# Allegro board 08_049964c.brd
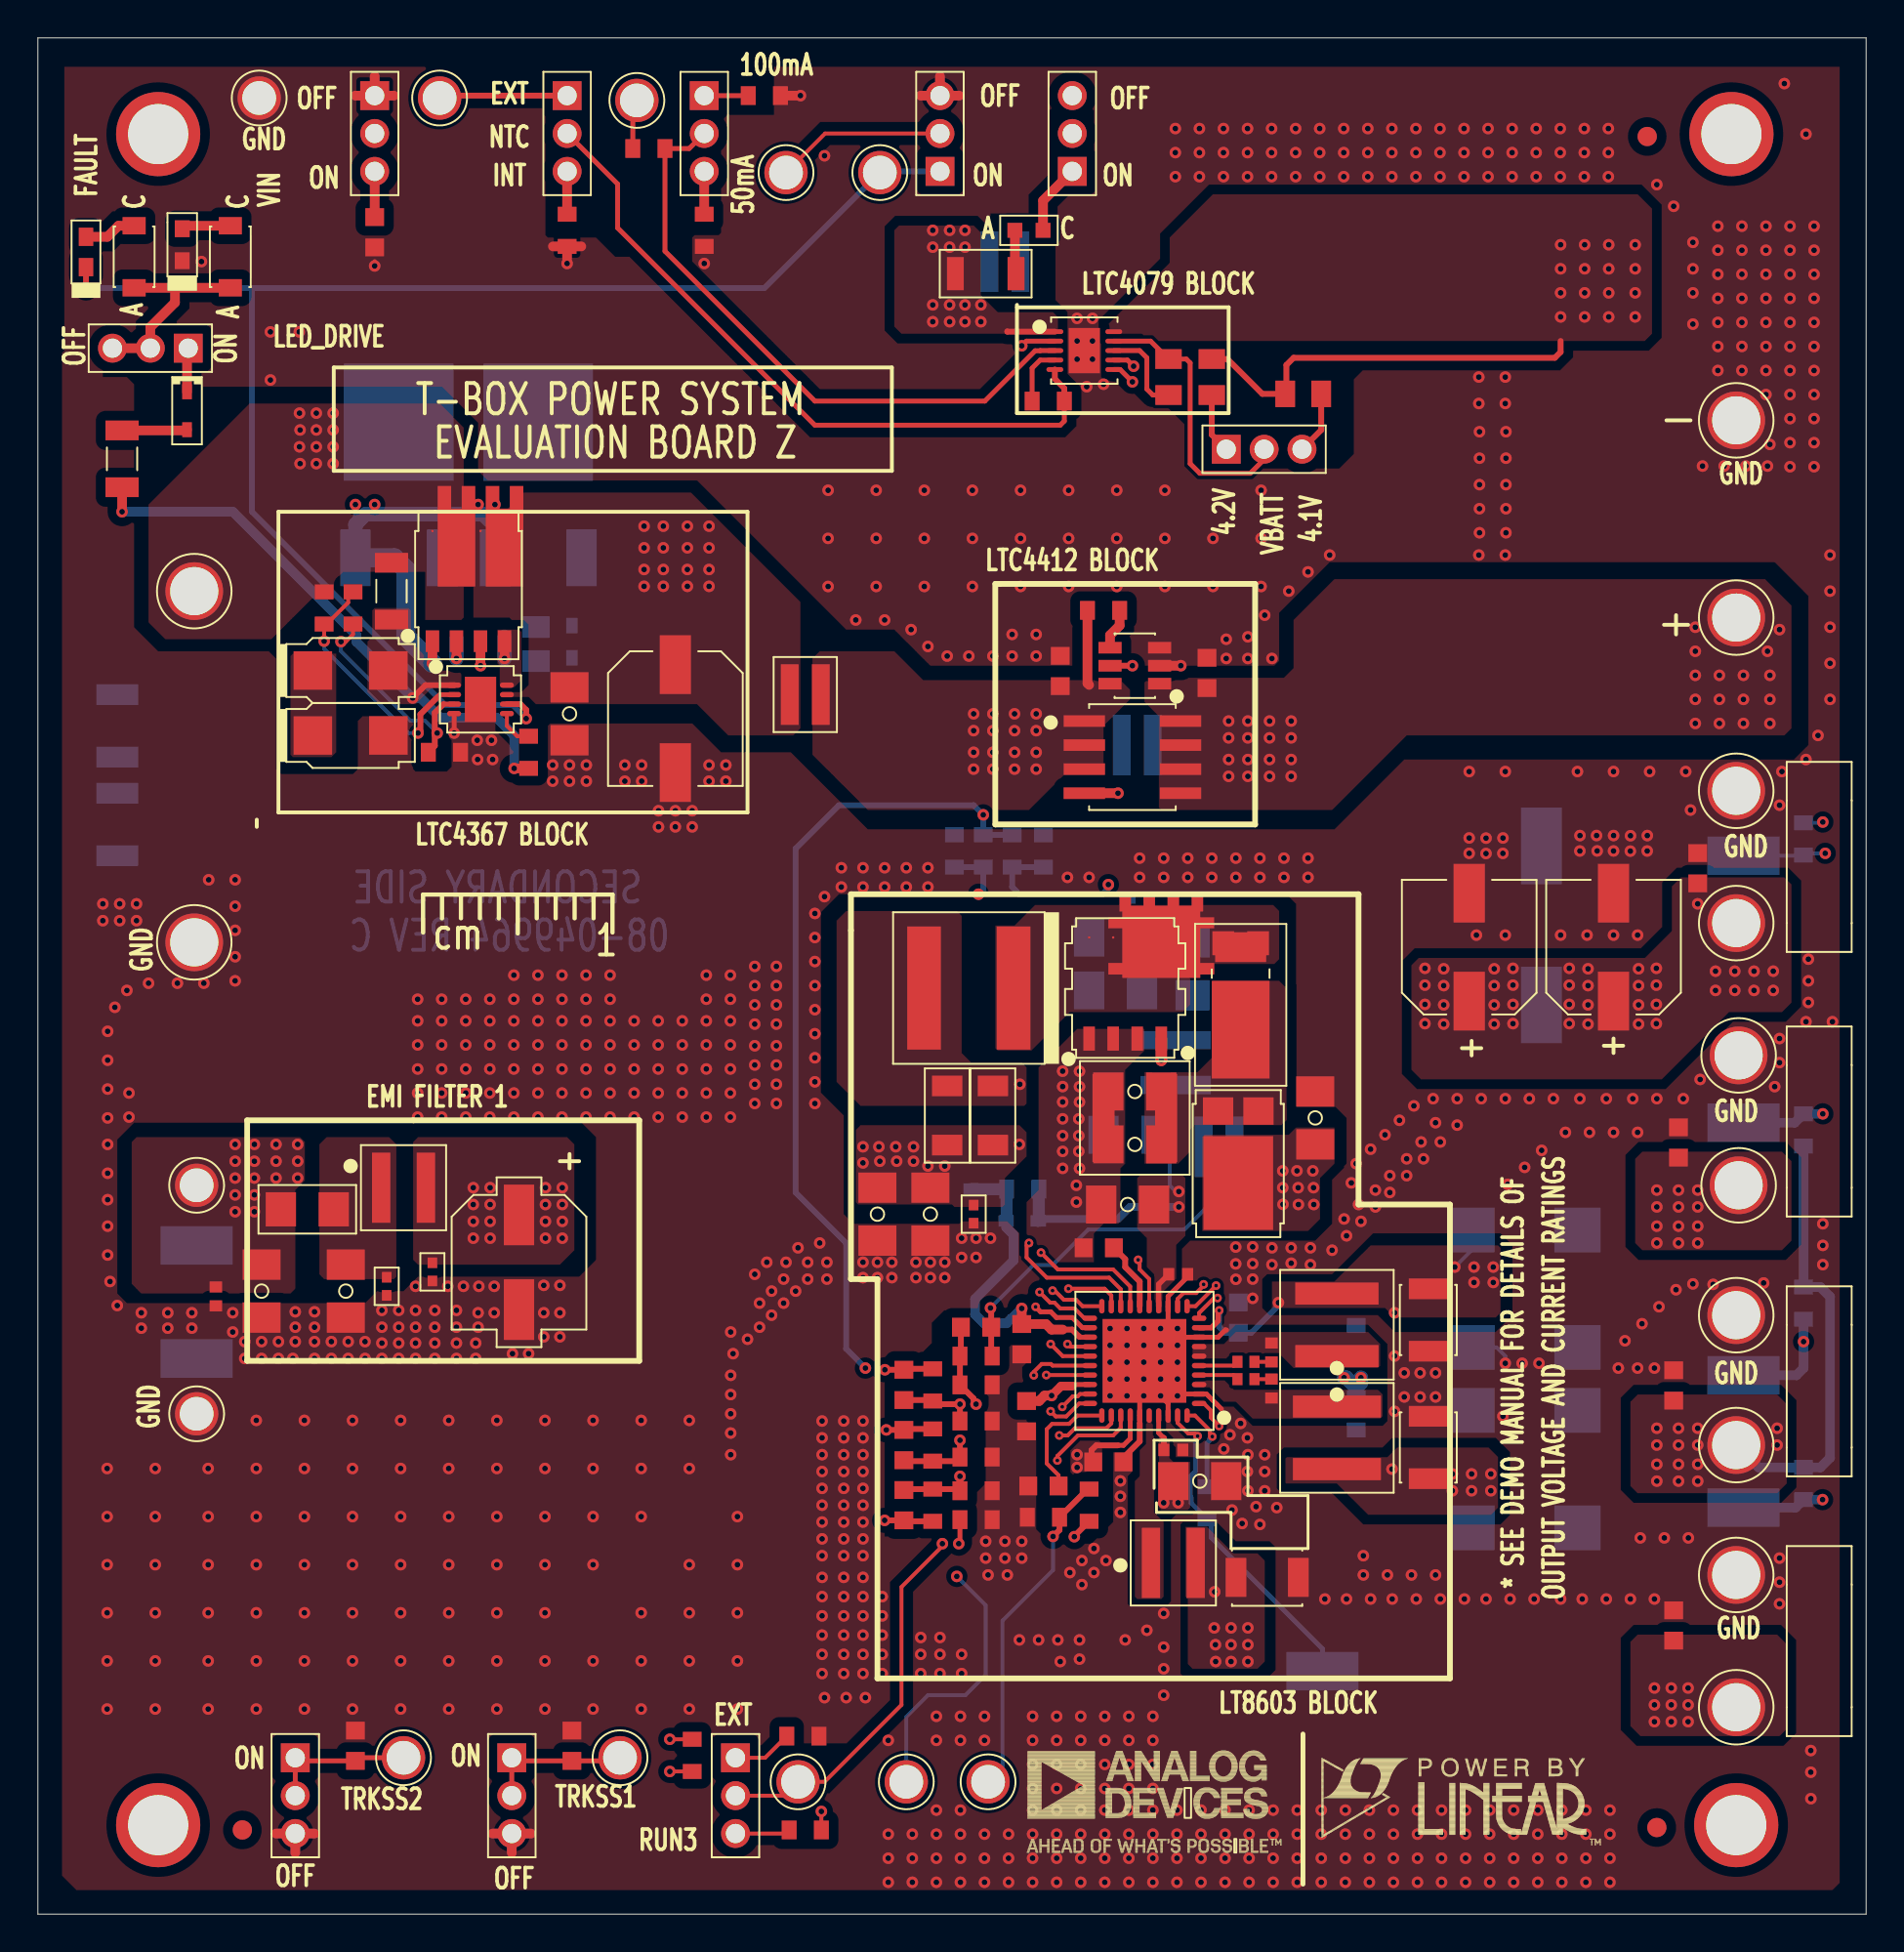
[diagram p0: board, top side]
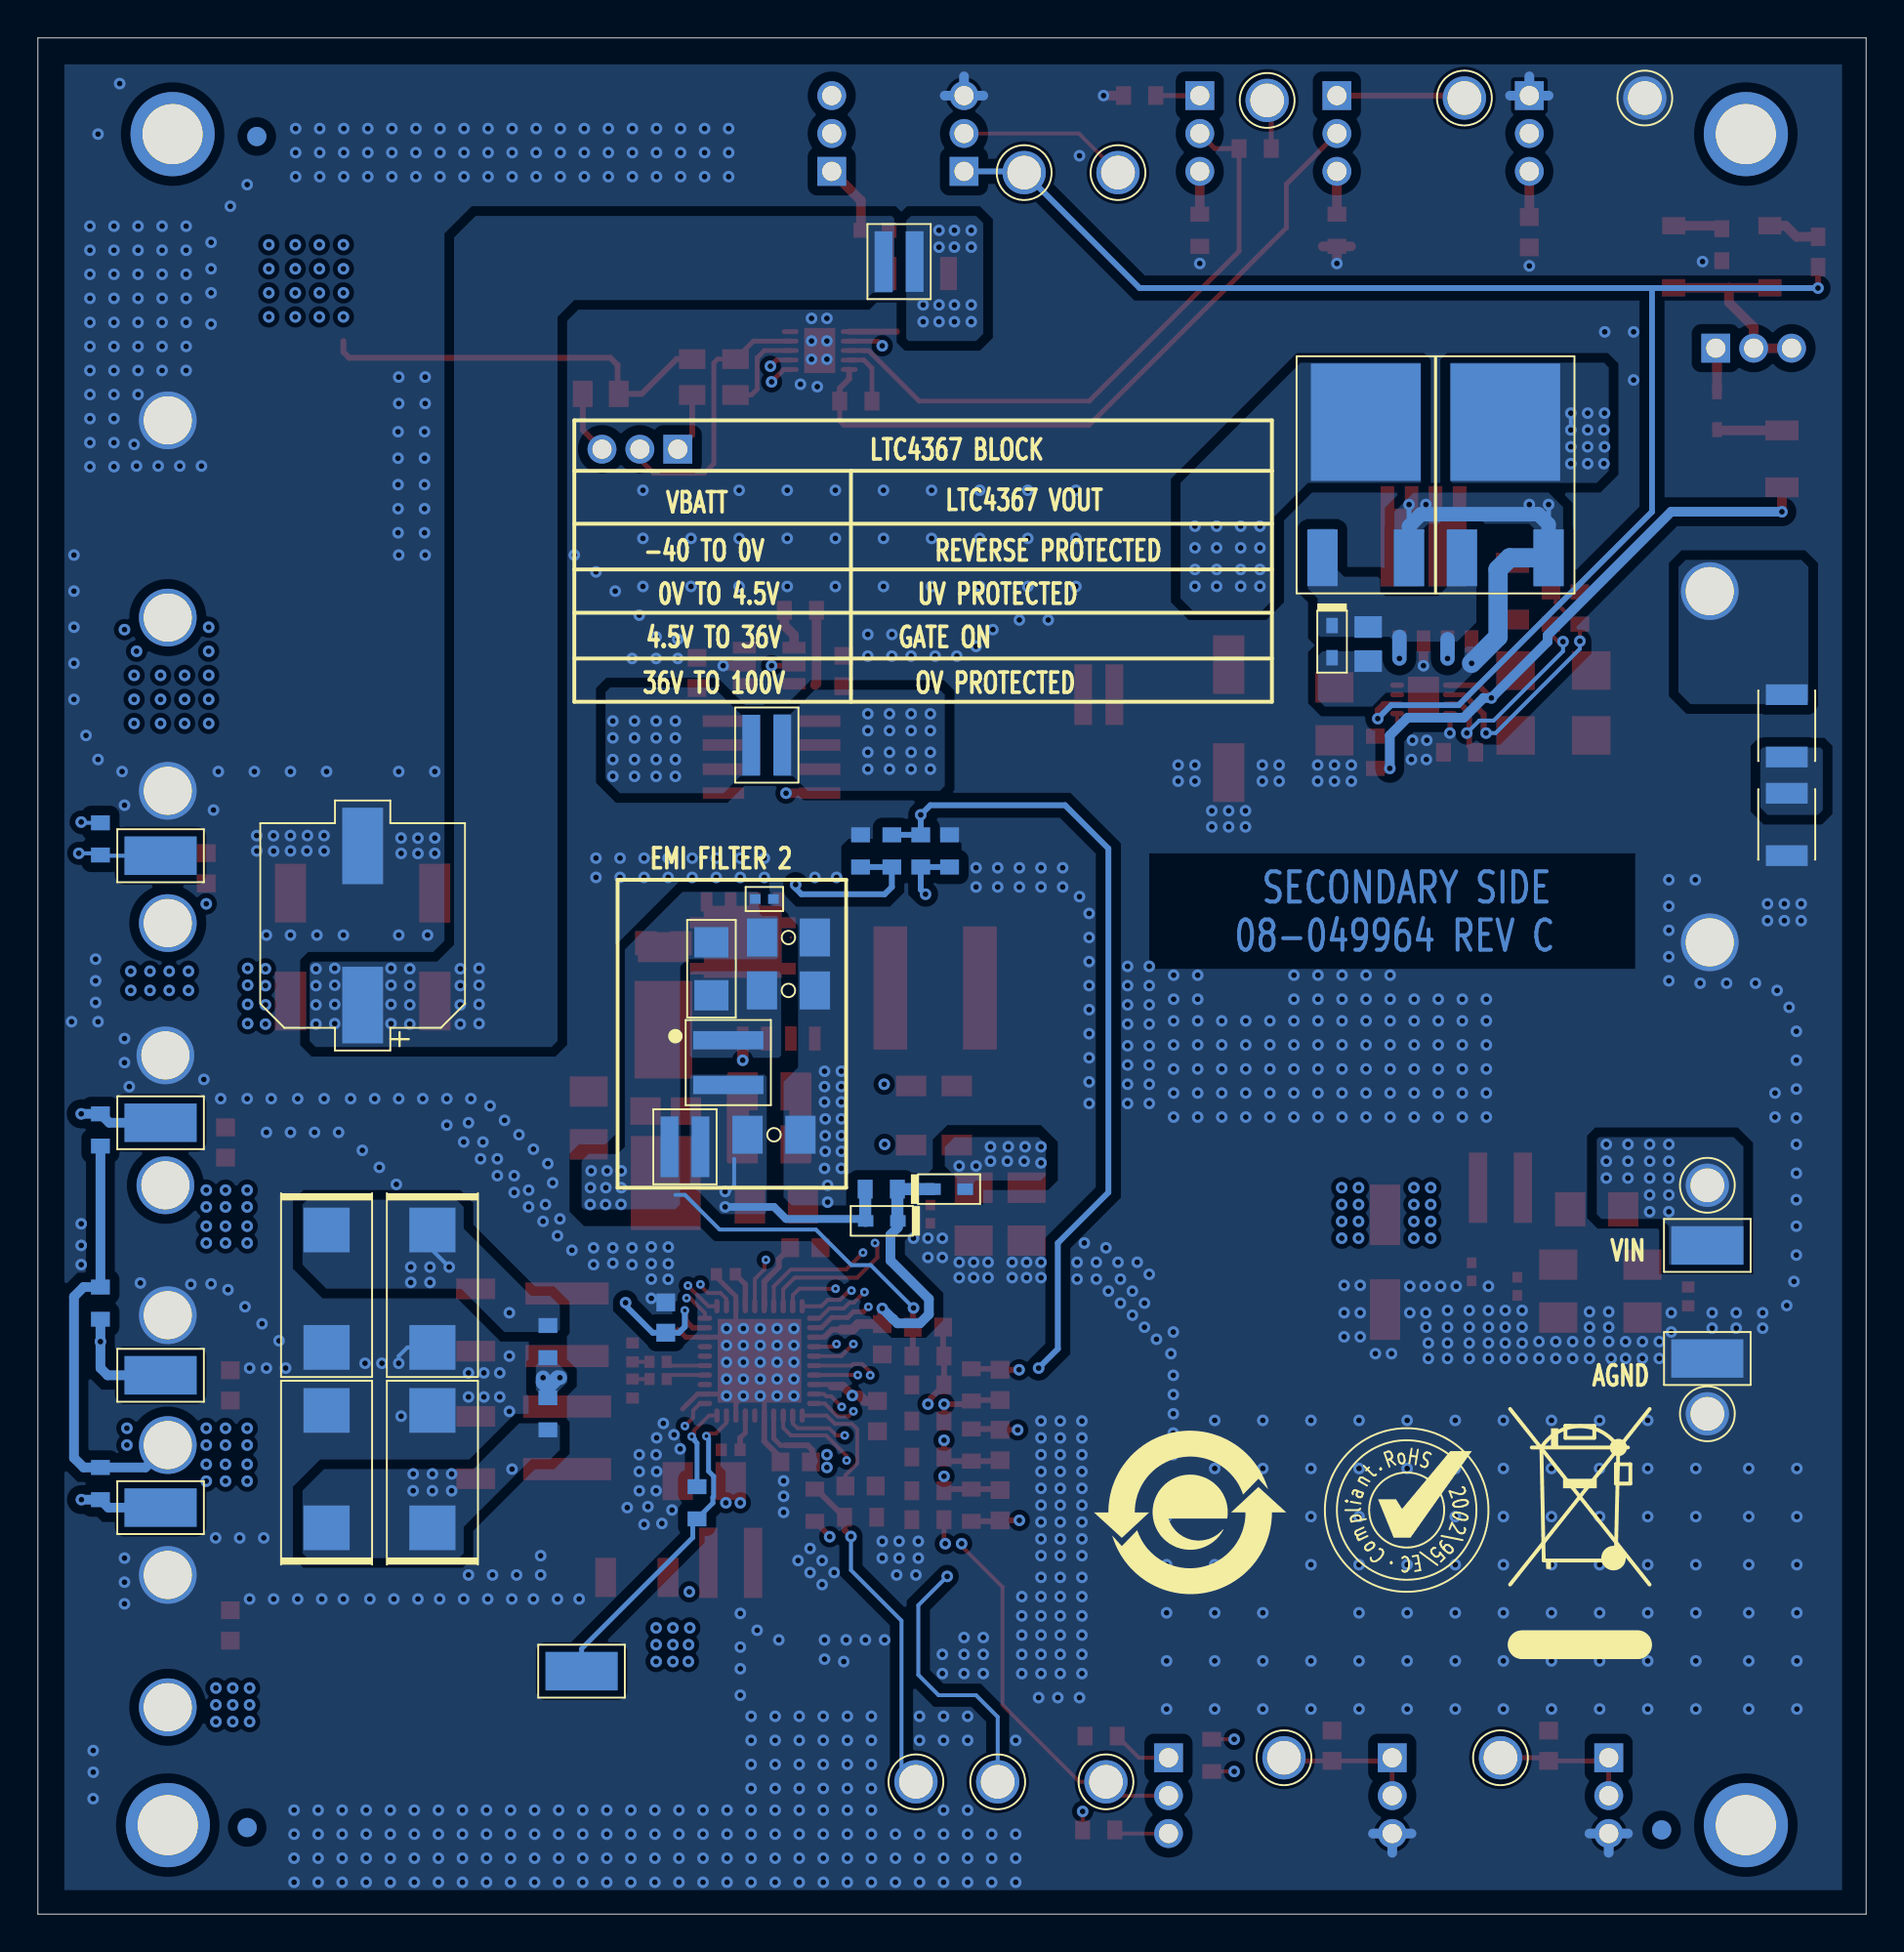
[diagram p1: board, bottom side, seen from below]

Outline 96.52 x 99.06 mm; copper layers: TOP, L2_GND, L3_PWR, BOTTOM. Coordinates in mm from the lower left corner of the outline.
Outline path: 0,99.06 0,0 96.52,0 96.52,99.06 0,99.06

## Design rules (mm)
constraint set DEFAULT: min track width 0.203

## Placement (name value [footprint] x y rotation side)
C1  10UF  [C1206H71]  44.32 36.96 90 top
C2  10UF  [C1206H71]  47.12 36.96 90 top
C4  0.047UF  [C0603]  17.78 88.8 90 top
C6  10UF  [C1206H71]  67.44 42.04 270 top
C7  0.1UF  [C0603]  61.72 65.53 270 top
C8  0.1UF  [C0603]  53.98 65.63 270 top
C9  0.1UF  [C0402]  9.4 32.61 90 top
C10  0.047UF  [C0603]  28.19 8.89 90 top
C11  0.047UF  [C0603]  16.76 8.89 90 top
C12  22UF  [CPLSMSQ260H217]  25.4 34.42 270 top
C13  10UF  [C1206H71]  11.81 32.89 90 top
C14  10UF  [C1206H71]  16.26 32.89 90 top
C15  10UF  [C1206H71]  61.34 22.86 180 top
C16  10UF  [C1206H71]  57.53 37.46 0 top
C17  1UF  [C0603]  51.94 30.35 270 top
C18  0.022uF  [C0603]  63.37 31.5 270 bottom
C19  4.7UF  [C0603]  52.2 26.29 90 top
C20  0.1UF  [C0402]  60.2 33.78 180 top
C21  4.7UF  [C0603]  56.01 35.18 0 top
C22  1500PF  [C0603]  53.09 22.61 180 top
C23  0.1UF  [C0402]  59.94 24.51 180 top
C24  0.1UF  [C0402]  65.13 27.75 270 top
C25  0.1UF  [C0402]  65.13 29.65 90 top
C26  10UF  [C0603]  56.52 23.88 180 top
C27  22PF  [C0603]  45.72 21.59 270 top
C28  4.7PF  [C0603]  45.72 27.94 90 top
C29  2.2PF  [C0603]  45.72 24.77 90 top
C30  0.022uF  [C0603]  49.53 30.99 0 top
C31  10UF  [C1206H71]  57.91 40.64 0 top
C32  100UF  [C1210H106]  64.9 17.78 180 top
C33  100UF  [C1210H106]  73.41 24.64 270 top
C35  47UF  [CPLSMSQ260H315]  75.56 51.05 90 top
C36  47UF  [CPLSMSQ260H315]  83.18 51.05 90 top
C37  0.1UF  [C0603]  86.36 27.91 270 top
C38  0.1UF  [C0603]  86.61 40.74 270 top
C39  0.1UF  [C0603]  86.36 15.24 270 top
C40  0.1UF  [C0603]  87.63 55.22 270 top
C41  1000PF  [C0805]  26.29 67.06 90 bottom
C42  10UF  [C1206H71]  28.07 63.37 90 top
C43  47UF  [CPLSMSQ260H315]  33.66 63.12 270 top
C44  100UF  [C1210H106]  73.41 31.37 90 top
C45  10uF  [C1210-2]  63.5 49.66 270 top
C46  330UF  [CPLSMSQ406H425]  79.38 52.2 90 bottom
C47  10UF  [C1206H71]  57.91 43.43 0 top
C48  1NF  [C0402H22]  49.4 36.96 90 top
C49  1NF  [C0402H22]  18.41 33.15 90 top
C50  1NF  [C0402H22]  20.83 33.91 90 top
C53  4.7UF  [C1210H87]  4.19 62.74 90 bottom
C54  4.7UF  [C1210H87]  4.19 57.53 90 bottom
C55  10UF  [C1206H71]  56.9 51.56 0 bottom
C56  10UF  [C1206H71]  56.9 48.77 0 bottom
C57  0.1uF  [C0402H22]  58.17 53.59 0 bottom
C58  330UF  [C7343-31]  81.28 23.49 90 bottom
C59  330UF  [C7343-31]  75.69 23.49 90 bottom
C60  330UF  [C7343-31]  81.28 33.02 270 bottom
C61  330UF  [C7343-31]  75.69 33.02 270 bottom
C62  10UF  [C1206H71]  57.66 41.15 0 bottom
CHARGER_EN  2308-2-00-80-00-00-07-0  [CNMILLMAX2308]  39.5 91.95 0 top
CHRG_LED  M22F2010305  [CNHDR1X3H207]  54.61 92.01 90 top
D1  PMEG060V050EPDZ  [SOT1289]  63.37 39.62 270 top
D2  PDS1040L  [POWERDI5]  63.5 48.01 180 top
D3  PMEG6002EB  [SOD523_B]  48.41 38.28 180 bottom
D4  SZ1SMA33AT3G  [SMA]  16.51 65.66 0 top
D5  SZ1SMA70AT3G  [SMA]  16.51 62.23 0 top
D6  BAS516,115  [SOD523F]  7.87 79.38 270 top
D7  CMJ2000 TR  [SOD123FL]  10.16 87.5 270 top
D8  CMJ2000 TR  [SOD123FL]  5.08 87.5 270 top
D9  PMEG6002EB  [SOD523_B]  51.97 36.6 0 bottom
D10  BZT52C15T-7  [SOD523_B]  28.19 67.18 270 bottom
DS1  LTST-C193KGKT-5A  [LED0603H12]  52.32 88.9 180 top
DS2  SML-D12P8WT86  [LED0603_A]  7.62 88.14 90 top
DS3  LS Q976-NR-1  [LED0603]  2.54 87.76 90 top
E1  50OHM AT 100MEGHZ  [L1206-3]  14.22 37.21 0 top
E3  50OHM AT 100MEGHZ  [L1206-3]  60.96 49.91 270 bottom
EN  M22F2010305  [CNHDR1X3H207]  47.62 92.01 90 top
FAULT  2308-2-00-80-00-00-07-0  [CNMILLMAX2308]  44.45 91.95 0 top
ICHARGE  M22F2010305  [CNHDR1X3H207]  35.18 96.01 270 top
L1  2.2UH  [LSMSQ295H122]  49.15 48.89 180 top
L2  220NH  [LSMSQ157H83_A]  19.3 38.35 0 top
L3  1uH  [LSMSQ157H83_A]  59.94 18.54 0 top
L4  4.7UH  [LSML208W216H122_A]  68.58 25.15 270 top
L5  2.2uH  [LSML208W216H122]  68.58 31.12 90 top
L8  4.7UH  [LSML208W216H122_A]  57.91 42.04 180 top
L9  220NH  [LSMSQ157H83_A]  60.07 44.96 270 bottom
LED_DRIVE  M22F2010305  [CNHDR1X3H207]  7.94 82.68 180 top
NOREF  -  [unnamed]  6.35 93.98 0 top
NOREF#2  -  [#2]  0 99.06 0 top
NOREF#3  -  [#2]  6.35 4.7 0 top
NOREF#4  -  [unnamed]  10.79 4.45 0 top
NOREF#5  -  [unnamed]  6.35 4.7 0 top
NOREF#6  -  [#2]  94.36 182.88 0 top
NOREF#7  -  [#2]  0 99.06 0 top
NOREF#8  -  [#2]  96.52 0 0 top
NOREF#9  -  [#2]  96.52 99.06 180 top
NOREF#10  -  [unnamed]  85.47 4.57 0 top
NOREF#11  -  [#2]  92.01 95.29 0 top
NOREF#12  -  [unnamed]  84.96 93.85 0 top
NOREF#13  -  [#2]  0 99.06 270 top
NOREF#14  -  [#2]  96.52 0 90 top
NOREF#15  -  [#2]  6.35 4.7 0 top
NOREF#16  -  [#2]  -185.17 276.35 0 top
NOREF#17  -  [#2]  -103.76 185.42 0 top
NOREF#18  -  [#2]  96.52 0 90 top
NOREF#19  -  [#2]  0 0 0 top
NOREF#20  -  [#2]  -251.59 -109.47 0 top
NOREF#21  -  [#2]  0 0 0 top
NOREF#22  -  [unnamed]  89.41 93.98 0 top
NOREF#23  -  [unnamed]  89.66 4.7 0 top
NOREF#24  -  [#2]  137.67 376.68 0 top
NOREF#25  -  [#2]  -196.09 82.04 0 top
NOREF#26  -  [#2]  -251.59 -109.47 0 top
NOREF#27  -  [#2]  49.4 115.57 0 top
NOREF#28  -  [#2]  65.41 42.93 0 top
NOREF#29  -  [#2]  0 0 0 top
NOREF#30  -  [#2]  -251.59 -109.47 0 top
NOREF#31  -  [#2]  25.4 49.78 270 top
NOREF#32  -  [#2]  196.98 209.55 0 top
NOREF#33  -  [#2]  35.69 21.21 180 bottom
NOREF#34  -  [#2]  24.26 21.34 180 bottom
NOREF#35  -  [unnamed]  10.79 4.45 180 bottom
NOREF#36  -  [#2]  5.84 30.35 180 bottom
NOREF#37  -  [unnamed]  84.96 93.85 180 bottom
NOREF#38  -  [unnamed]  85.47 4.57 180 bottom
NTC  2308-2-00-80-00-00-07-0  [CNMILLMAX2308]  21.21 95.89 0 top
P2  M22F2010305  [CNHDR1X3H207]  27.94 96.01 270 top
P5  M22F2010305  [CNHDR1X3H207]  25.02 8.25 270 top
P6  M22F2010305  [CNHDR1X3H207]  13.59 8.25 270 top
P13  M22F2010305  [CNHDR1X3H207]  62.74 77.34 0 top
P14  M22F2010305  [CNHDR1X3H207]  36.83 8.25 270 top
PG1  5019  [CNKEY5019]  90.04 28.45 180 bottom
PG2  5019  [CNKEY5019]  90.04 41.78 180 bottom
PG3  5019  [CNKEY5019]  90.04 21.46 180 bottom
PG4  5019  [CNKEY5019]  90.04 55.88 180 bottom
POREN  5019  [CNKEY5019]  67.82 12.83 180 bottom
PROG  2308-2-00-80-00-00-07-0  [CNMILLMAX2308]  31.62 95.76 0 top
Q1  DMTH6009LPS-13  [POWERDI5060-8]  57.4 48.89 0 top
Q2  BUK7K89-100EX  [SOT1205]  22.73 70.48 0 top
Q3  FDS4141-F085  [SO8]  57.79 61.09 270 top
Q4  SQD25N15-52_GE3  [DPAK]  19.05 76.33 180 bottom
Q5  NVD5C688NLT4G  [DPAK]  26.42 76.33 180 bottom
R1  0.005  [R1206H38]  50.42 42.16 270 top
R2  100K  [R0603]  32.26 93.22 0 top
R3  0  [R0603]  51.99 38.28 180 bottom
R4  3.01K  [R0603]  38.35 96.01 180 top
R5  100K  [R0603]  53.34 79.88 180 top
R6  100K  [R0603]  27.94 88.9 90 top
R7  5.9K  [R0603]  35.18 88.9 90 top
R8  412K  [R0805]  59.69 81.15 90 top
R9  1.07MEG  [R0805]  61.98 81.15 90 top
R11  12K  [R1206_A]  50.04 86.61 180 top
R13  560K  [R0603]  56.26 68.83 0 top
R14  24.9K  [R0603]  93.22 32.26 90 bottom
R15  24.9K  [R0603]  93.22 41.4 270 bottom
R17  10K  [R0603]  40.51 4.45 180 top
R18  24.9K  [R0603]  93.22 22.73 90 bottom
R19  24.9K  [R0603]  93.22 56.77 90 bottom
R20  0  [R0402]  63.78 28.24 0 top
R21  0  [R0402]  63.78 29.16 0 top
R22  2MEG  [R0603]  34.54 8.38 90 top
R23  0  [R0603]  51.44 56.13 270 bottom
R24  0  [R0603]  53.09 56.13 270 bottom
R25  100K  [R0603]  61.72 21.72 90 bottom
R26  100K  [R0603]  53.09 20.95 180 top
R27  0  [R0603]  49.91 56.13 90 bottom
R28  0  [R0603]  48.39 56.13 90 bottom
R29  0  [R0603]  55.5 21.59 90 top
R31  30.1K  [R0603]  49.53 20.83 180 top
R32  475K  [R0603]  47.24 21.59 270 top
R33  562K  [R0603]  47.24 24.77 90 top
R34  806K  [R0603]  47.24 27.94 90 top
R35  3.3MEG  [R0603]  49.53 29.46 0 top
R36  150K  [R0603]  49.53 22.35 0 top
R37  365K  [R0603]  49.53 27.94 180 top
R38  200K  [R0603]  49.53 24.13 0 top
R39  200K  [R0603]  49.53 26.03 0 top
R40  0  [R0603]  69.6 30.23 270 bottom
R41  1K  [R1206]  4.44 76.83 270 top
R42  510K  [R0603]  25.91 61.34 90 top
R43  2.37MEG  [R0603]  15.11 68.96 270 top
R44  261K  [R0603]  16.64 68.96 270 top
R45  37.4K  [R0603]  21.46 61.34 0 top
R49  1.02MEG  [R0805]  66.8 80.26 180 top
R50  0  [R0612]  40.51 64.39 180 top
R51  0  [R0612]  51.05 87.25 180 bottom
R52  0  [R0612]  58.04 61.72 0 bottom
R53  0  [R0612]  62.36 40.51 0 bottom
R54  0  [R0603]  69.6 26.42 270 bottom
R55  100K  [R0603]  40.39 9.4 0 top
R57  1K  [R1206]  18.67 69.85 90 top
R58  0.005  [R1206H38]  48.01 42.16 270 top
RST_N  2308-2-00-80-00-00-07-0  [CNMILLMAX2308]  45.85 6.98 0 top
RUN3  2308-2-00-80-00-00-07-0  [CNMILLMAX2308]  40.13 6.98 0 top
SYNC  2308-2-00-80-00-00-07-0  [CNMILLMAX2308]  50.16 6.98 0 top
TIMER  M22F2010305  [CNHDR1X3H207]  17.78 96.01 270 top
TP1  2501-2-00-80-00-00-07-0  [CNMILLMAX2501]  89.66 78.87 0 top
TP6  2308-2-00-80-00-00-07-0  [CNMILLMAX2308]  11.68 95.89 0 top
TP35  2501-2-00-80-00-00-07-0  [CNMILLMAX2501]  89.66 31.62 0 top
TP37  2501-2-00-80-00-00-07-0  [CNMILLMAX2501]  89.79 45.34 0 top
TP39  2501-2-00-80-00-00-07-0  [CNMILLMAX2501]  89.66 17.91 0 top
TP41  2501-2-00-80-00-00-07-0  [CNMILLMAX2501]  89.66 59.31 0 top
TP42  2308-2-00-80-00-00-07-0  [CNMILLMAX2308]  8.38 26.42 0 top
TP43  2501-2-00-80-00-00-07-0  [CNMILLMAX2501]  8.25 51.31 0 top
TP44  5019  [CNKEY5019]  8.38 35.31 180 bottom
TP45  5019  [CNKEY5019]  8.38 29.34 180 bottom
TRKSS1  2308-2-00-80-00-00-07-0  [CNMILLMAX2308]  30.73 8.25 0 top
TRKSS2  2308-2-00-80-00-00-07-0  [CNMILLMAX2308]  19.3 8.25 0 top
U1  LTC4079IDD#TRPBF  [DFN10_3X3_PAD2_38X1_64]  55.25 82.55 270 top
U2  LTC4412HVIS6#TRPBF  [TSOT23_6]  57.91 65.91 90 top
U3  LT8603IUJ#TRPBF  [QFN40_6X6_PAD4_42X4_42]  58.42 29.21 90 top
U4  LTC4367HDD-1#TRPBF  [DFN8_3X3_PAD2_38X1_65]  23.37 64.14 270 top
VBACKUP  2501-2-00-80-00-00-07-0  [CNMILLMAX2501]  89.66 68.45 180 top
VBATT  2501-2-00-80-00-00-07-0  [CNMILLMAX2501]  8.25 69.85 0 top
VIN  2308-2-00-80-00-00-07-0  [CNMILLMAX2308]  8.38 38.48 0 top
VOUT1  2501-2-00-80-00-00-07-0  [CNMILLMAX2501]  89.66 24.76 0 top
VOUT2  2501-2-00-80-00-00-07-0  [CNMILLMAX2501]  89.79 38.48 0 top
VOUT3  2501-2-00-80-00-00-07-0  [CNMILLMAX2501]  89.66 10.92 0 top
VOUT4  2501-2-00-80-00-00-07-0  [CNMILLMAX2501]  89.66 52.32 0 top

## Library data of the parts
C1 C2 C6 C13-C16 C31 C42 C47 C55 C56 C62 = CAP: Tolerance: 20; User Part Number: UPN; alternate symbols: (); part number: CAP_SM-10UF,50V,20,E034660,C1206H71; tolerance: 20
C4 C10 C11 = CAP: User Part Number: UPN; Tolerance: 5; alternate symbols: (); part number: CAP_SM-0.047UF,50V,5,E033302,C0603; tolerance: 5
C7 C8 C37-C40 = CAP: User Part Number: UPN; Tolerance: 10; alternate symbols: (); part number: CAP_SM-0.1UF,50V,10,E033467,C0603; tolerance: 10
C9 C20 C23 = CAP: User Part Number: UPN; Tolerance: 10; alternate symbols: (); part number: CAP_SM-0.1UF,50V,10,E034665,C0402; tolerance: 10
C12 = CAPP: User Part Number: UPN; Tolerance: 20; alternate symbols: (); part number: CAPP_SM-22UF,50V,20,E032849,CPLSMSQ260H217; tolerance: 20
C17 = CAP: User Part Number: UPN; Tolerance: 10; alternate symbols: (); part number: CAP_SM-1UF,50V,10,E034666,C0603; tolerance: 10
C18 C30 = CAP: User Part Number: UPN; Tolerance: 10; alternate symbols: (); part number: CAP_SM-0.022UF,16V,10,E000327,C0603; tolerance: 10
C19 C21 = CAP: User Part Number: UPN; Tolerance: 10; alternate symbols: (); part number: CAP_SM-4.7UF,10V,10,E034981,C0603; tolerance: 10
C22 = CAP: User Part Number: UPN; Tolerance: 10; alternate symbols: (); part number: CAP_SM-1500PF,50V,10,E030854,C0603; tolerance: 10
C24 C25 = CAP: User Part Number: UPN; Tolerance: 10; alternate symbols: (); part number: CAP_SM-0.1UF,25V,10,E033331,C0402; tolerance: 10
C26 = CAP: User Part Number: UPN; Tolerance: 20; alternate symbols: (); part number: CAP_SM-10UF,10V,20,E033351,C0603; tolerance: 20
C27 = CAP: User Part Number: UPN; Tolerance: 5; alternate symbols: (); part number: CAP_SM-22PF,6.3V,5,E034667,C0603; tolerance: 5
C28 = CAP: User Part Number: UPN; Tolerance: 0.25PF; alternate symbols: (); part number: CAP_SM-4.7PF,25V,0.25PF,E034668,C0603; tolerance: 0.25PF
C29 = CAP: User Part Number: UPN; Tolerance: 0.25PF; alternate symbols: (); part number: CAP_SM-2.2PF,50V,0.25PF,E033413,C0603; tolerance: 0.25PF
C32 C33 C44 = CAP: Tolerance: 20; User Part Number: UPN; alternate symbols: (); part number: CAP_SM-100UF,6.3V,20,E034669,C1210H106; tolerance: 20
C35 C36 C43 = CAPP: Tolerance: 20; User Part Number: UPN; alternate symbols: (); part number: CAPP_SM-47UF,50V,20,E032848,CPLSMSQ260H315; tolerance: 20
C41 = CAP: User Part Number: UPN; Tolerance: 10; alternate symbols: (); part number: CAP_SM-1000PF,100V,10,E026082,C0805; tolerance: 10
C45 = CAP: Tolerance: 10; User Part Number: UPN; alternate symbols: (); part number: CAP_SM-10UF,50V,10,E019010,C1210-2; tolerance: 10
C46 = CAPP: User Part Number: UPN; Tolerance: 20; alternate symbols: (); part number: CAPP_SM-330UF,50V,20,E034654,CPLSMSQ406H425; tolerance: 20
C48-C50 = CAP: Tolerance: 10; User Part Number: UPN; alternate symbols: (); part number: CAP_SM-1NF,50V,10,E033487,C0402H22; tolerance: 10
C53 C54 = CAP: Tolerance: 10; User Part Number: UPN; alternate symbols: (); part number: CAP_SM-4.7UF,100V,10,E033812,C1210H87; tolerance: 10
C57 = CAP: Tolerance: 10; User Part Number: UPN; alternate symbols: (); part number: CAP_SM-0.1UF,50V,10,E018452,C0402H22; tolerance: 10
C58-C61 = CAPP: Tolerance: 20; User Part Number: UPN; alternate symbols: (); part number: CAPP_SM-330UF,6.3V,20,E034856,C7343-31; tolerance: 20
CHARGER_EN FAULT NTC PROG RST_N RUN3 SYNC TP6 TP42 TRKSS1 TRKSS2 VIN = CNTP1P: User Part Number: UPN; Tolerance: N/A; alternate symbols: (); part number: CNTP1P_TH-2308-2-00-80-00-00-07-0,E030692,CNMILLMAX2308; tolerance: N/A
CHRG_LED EN ICHARGE LED_DRIVE P2 P5 P6 P13 P14 TIMER = CN3P: User Part Number: UPN; Tolerance: N/A; alternate symbols: (); part number: CN3P_TH-M22F2010305,E017879,CNHDR1X3H207; tolerance: N/A
D1 = DIOSCHOTTKY_3P: User Part Number: UPN; Tolerance: N/A; alternate symbols: (); part number: DIOSCHOTTKY_3P_SM-PMEG060V050EPDZ,60V,N/A,E033414,SOT1289; tolerance: N/A
D2 = DIOSCHOTTKY_3P: Tolerance: N/A; User Part Number: UPN; alternate symbols: (); part number: DIOSCHOTTKY_3P_SM-PDS1040L,40V,N/A,E006430,POWERDI5; tolerance: N/A
D3 D9 = DIOSCHOTTKY: Tolerance: N/A; User Part Number: UPN; alternate symbols: (); part number: DIOSCHOTTKY_SM-PMEG6002EB,60V,N/A,E033364,SOD523_B; tolerance: N/A
D4 = DIOZNR: User Part Number: UPN; Tolerance: N/A; alternate symbols: (); part number: DIOZNR_SM-SZ1SMA33AT3G,33V,N/A,E034919,SMA; tolerance: N/A
D5 = DIOZNR: User Part Number: UPN; Tolerance: N/A; alternate symbols: (); part number: DIOZNR_SM-SZ1SMA70AT3G,70V,N/A,E034648,SMA; tolerance: N/A
D6 = DIO: Tolerance: N/A; User Part Number: UPN; alternate symbols: (); part number: DIO_SM-BAS516,115,100V,N/A,E013667,SOD523F; tolerance: N/A
D7 D8 = DIO: User Part Number: UPN; Tolerance: N/A; alternate symbols: (); part number: DIO_SM-CMJ2000 TR,100V,N/A,E032855,SOD123FL; tolerance: N/A
D10 = DIOZNR: Tolerance: 6; User Part Number: UPN; alternate symbols: (); part number: DIOZNR_SM-BZT52C15T-7,15V,6,E032822,SOD523_B; tolerance: 6
DS1 = DIOLED: User Part Number: UPN; Tolerance: N/A; alternate symbols: (); part number: DIOLED_SM-LTST-C193KGKT-5A,N/A,N/A,E020972,LED0603H12; tolerance: N/A
DS2 = DIOLED: User Part Number: UPN; Tolerance: N/A; alternate symbols: (); part number: DIOLED_SM-SML-D12P8WT86,2.2V,N/A,E027457,LED0603_A; tolerance: N/A
DS3 = DIOLED: Tolerance: N/A; User Part Number: UPN; alternate symbols: (); part number: DIOLED_SM-LS Q976-NR-1,2V,N/A,E027231,LED0603; tolerance: N/A
E1 E3 = FERRITE: Tolerance: 12.5OHM; User Part Number: UPN; alternate symbols: (); part number: FERRITE_SM-50OHM AT 100MEGHZ,12.5OHM,E034650,L1206-3; tolerance: 12.5OHM
L1 = IND: User Part Number: UPN; Tolerance: 20; alternate symbols: (); part number: IND_SM-2.2UH,20,E032779,LSMSQ295H122; tolerance: 20
L2 L9 = IND: User Part Number: UPN; Tolerance: 20; alternate symbols: (); part number: IND_SM-220NH,20,E032809,LSMSQ157H83_A; tolerance: 20
L3 = IND: User Part Number: UPN; Tolerance: 20; alternate symbols: (); part number: IND_SM-1UH,20,E022556,LSMSQ157H83_A; tolerance: 20
L4 L8 = IND: Tolerance: 20; User Part Number: UPN; alternate symbols: (); part number: IND_SM-4.7UH,20,E032776,LSML208W216H122_A; tolerance: 20
L5 = IND: Tolerance: 20; User Part Number: UPN; alternate symbols: (); part number: IND_SM-2.2UH,20,E017908,LSML208W216H122; tolerance: 20
PG1-PG4 POREN TP44 TP45 = CNTP1P: User Part Number: UPN; Tolerance: N/A; alternate symbols: (); part number: CNTP1P_SM-5019,E021431,CNKEY5019; tolerance: N/A
Q1 = TRANNMOSFET_V15: User Part Number: UPN; Tolerance: N/A; alternate symbols: (); part number: TRANNMOSFET_V15_SM-DMTH6009LPS-13,E032841,POWERDI5060-8; tolerance: N/A
Q2 = TRANNMOSFET_DUAL: Tolerance: N/A; User Part Number: UPN; alternate symbols: (); part number: TRANNMOSFET_DUAL_SM-BUK7K89-100EX,E032967,SOT1205; tolerance: N/A
Q3 = TRANPMOSFET_V9: Tolerance: N/A; User Part Number: UPN; alternate symbols: (); part number: TRANPMOSFET_V9_SM-FDS4141-F085,E032945,SO8; tolerance: N/A
Q4 = TRANNMOSFET_V21: Tolerance: N/A; User Part Number: UPN; alternate symbols: (); part number: TRANNMOSFET_V21_SM-SQD25N15-52_GE3,E034679,DPAK; tolerance: N/A
Q5 = TRANNMOSFET_V21: Tolerance: N/A; User Part Number: UPN; alternate symbols: (); part number: TRANNMOSFET_V21_SM-NVD5C688NLT4G,E034677,DPAK; tolerance: N/A
R1 R58 = RES: Tolerance: 1; User Part Number: UPN; alternate symbols: (); part number: RES_SM-0.005,E033411,1W,1,R1206H38; tolerance: 1
R2 R5 R6 R25 R26 R55 = RES: User Part Number: UPN; Tolerance: 1; alternate symbols: (R0603L); part number: RES_SM-100K,E010279,1/10W,1,R0603; tolerance: 1
R3 R23 R28 R40 R54 = RES: User Part Number: UPN; Tolerance: 5; alternate symbols: (R0603L); part number: RES_SM-0,E006826,1/10W,5,R0603; tolerance: 5
R4 = RES: User Part Number: UPN; Tolerance: 1; alternate symbols: (); part number: RES_SM-3.01K,E034678,1/10W,1,R0603; tolerance: 1
R7 = RES: User Part Number: UPN; Tolerance: 0.1; alternate symbols: (R0603L); part number: RES_SM-5.9K,E024298,1/10W,0.1,R0603; tolerance: 0.1
R8 = RES: User Part Number: UPN; Tolerance: 0.1; alternate symbols: (); part number: RES_SM-412K,E033587,1/8W,0.1,R0805; tolerance: 0.1
R9 = RES: User Part Number: UPN; Tolerance: 1; alternate symbols: (); part number: RES_SM-1.07MEG,E032844,1/8W,1,R0805; tolerance: 1
R11 = RES: User Part Number: UPN; Tolerance: 5; alternate symbols: (); part number: RES_SM-12K,E032857,1/2W,5,R1206_A; tolerance: 5
R13 = RES: User Part Number: UPN; Tolerance: 1; alternate symbols: (); part number: RES_SM-560K,E033371,1/10W,1,R0603; tolerance: 1
R14 R15 R18 R19 = RES: User Part Number: UPN; Tolerance: 0.1; alternate symbols: (R0603L); part number: RES_SM-24.9K,E024281,1/10W,0.1,R0603; tolerance: 0.1
R17 = RES: User Part Number: UPN; Tolerance: 1; alternate symbols: (R0603L); part number: RES_SM-10K,E003671,1/10W,1,R0603; tolerance: 1
R20 R21 = RES: User Part Number: UPN; Tolerance: 5; alternate symbols: R0402L; part number: RES_SM-0,E003438,N/A,5,R0402; tolerance: 5
R22 = RES: User Part Number: UPN; Tolerance: 1; alternate symbols: (); part number: RES_SM-2MEG,E034670,1/10W,1,R0603; tolerance: 1
R24 R27 R29 = RES: User Part Number: UPN; Tolerance: 1; alternate symbols: (R0603L); part number: RES_SM-0,E004207,1/16W,1,R0603; tolerance: 1
R31 = RES: User Part Number: UPN; Tolerance: 1; alternate symbols: (R0603L); part number: RES_SM-30.1K,E011129,1/10W,1,R0603; tolerance: 1
R32 = RES: User Part Number: UPN; Tolerance: 1; alternate symbols: (); part number: RES_SM-475K,E032846,1/10W,1,R0603; tolerance: 1
R33 = RES: User Part Number: UPN; Tolerance: 1; alternate symbols: (); part number: RES_SM-562K,E032843,1/10,1,R0603; tolerance: 1
R34 = RES: User Part Number: UPN; Tolerance: 1; alternate symbols: (); part number: RES_SM-806K,E033372,1/10W,1,R0603; tolerance: 1
R35 = RES: User Part Number: UPN; Tolerance: 1; alternate symbols: (); part number: RES_SM-3.3MEG,E034671,1/10W,1,R0603; tolerance: 1
R36 = RES: User Part Number: UPN; Tolerance: 1; alternate symbols: (R0603L); part number: RES_SM-150K,E003672,1/10W,1,R0603; tolerance: 1
R37 = RES: User Part Number: UPN; Tolerance: 1; alternate symbols: (R0603L); part number: RES_SM-365K,E013444,1/10W,1,R0603; tolerance: 1
R38 R39 = RES: User Part Number: UPN; Tolerance: 1; alternate symbols: (R0603L); part number: RES_SM-200K,E015343,1/10W,1,R0603; tolerance: 1
R41 R57 = RES: User Part Number: UPN; Tolerance: 1; alternate symbols: (); part number: RES_SM-1K,E003198,1/4W,1,R1206; tolerance: 1
R42 = RES: User Part Number: UPN; Tolerance: 1; alternate symbols: (); part number: RES_SM-510K,E033373,1/10W,1,R0603; tolerance: 1
R43 = RES: User Part Number: UPN; Tolerance: 1; alternate symbols: (); part number: RES_SM-2.37MEG,E032825,1/10W,1,R0603; tolerance: 1
R44 = RES: User Part Number: UPN; Tolerance: 1; alternate symbols: (); part number: RES_SM-261K,E032826,1/10W,1,R0603; tolerance: 1
R45 = RES: User Part Number: UPN; Tolerance: 0.1; alternate symbols: (R0603L); part number: RES_SM-37.4K,E024283,1/10W,0.1,R0603; tolerance: 0.1
R49 = RES: User Part Number: UPN; Tolerance: 1; alternate symbols: (); part number: RES_SM-1.02MEG,E032845,1/8W,1,R0805; tolerance: 1
R50-R53 = RES: User Part Number: UPN; Tolerance: N/A; alternate symbols: (); part number: RES_SM-0,E034651,3/4W,N/A,R0612; tolerance: N/A
TP1 TP35 TP37 TP39 TP41 TP43 VBACKUP VBATT VOUT1-VOUT4 = CNTP1P: User Part Number: UPN; Tolerance: N/A; alternate symbols: (); part number: CNTP1P_TH-2501-2-00-80-00-00-07-0,E031108,CNMILLMAX2501; tolerance: N/A
U1 = LINLTC4079: Tolerance: N/A; User Part Number: UPN; alternate symbols: (); part number: LINLTC4079_SM-LTC4079IDD#TRPBF,E032573,DFN10_3X3_PAD2_38X1_64; tolerance: N/A
U2 = LINLTC4412: User Part Number: UPN; Tolerance: N/A; alternate symbols: (); part number: LINLTC4412_SM-LTC4412HVIS6#TRPBF,E032812,TSOT23_6; tolerance: N/A
U3 = ICLT8603: Tolerance: N/A; User Part Number: UPN; alternate symbols: (); part number: ICLT8603_SM-LT8603IUJ#TRPBF,E032577,QFN40_6X6_PAD4_42X4_42; tolerance: N/A
U4 = LINLTC4367: User Part Number: UPN; Tolerance: N/A; alternate symbols: (); part number: LINLTC4367_SM-LTC4367HDD-1#TRPBF,E032574,DFN8_3X3_PAD2_38X1_65; tolerance: N/A

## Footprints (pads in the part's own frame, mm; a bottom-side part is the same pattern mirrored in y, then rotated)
C0402
  rect 0.584x0.66 smd: 1(-0.5,0) 2(0.5,0)
C0402H22
  rect 0.559x0.508 smd: 1(-0.479,0) 2(0.479,0)
C0603
  rect 0.94x0.991 smd: 1(-0.8,0) 2(0.8,0)
C0805
  rect 1.143x1.448 smd: 1(-0.9,0) 2(0.9,0)
C1206H71
  rect 1.6x2.007 smd: 1(-1.397,0) 2(1.397,0)
C1210-2
  rect 1.575x2.692 smd: 1(-1.397,0) 2(1.397,0)
C1210H87
  rect 1.092x2.21 smd: 1(-1.646,0) 2(1.646,0)
C1210H106
  rect 1.092x2.057 smd: 1(-1.646,0) 2(1.646,0)
C7343-31
  rect 2.362x2.438 smd: N(3.1,0) P(-3.1,0)
CNHDR1X3H207
  rect 1.524x1.524 hole 1.016: 1(0,0)
  round 1.524 hole 1.016: 2(2,0) 3(4,0)
CNKEY5019
  rect 3.81x2.032 smd: 1(0,0)
CNMILLMAX2308
  round 2.286 hole 1.778: 1(0,0)
CNMILLMAX2501
  round 3.048 hole 2.54: 1(0,0)
CPLSMSQ260H217
  rect 3.2x1.6 smd: N(2.5,0) P(-2.5,0)
CPLSMSQ260H315
  rect 3.099x1.651 smd: N(2.85,0) P(-2.85,0)
CPLSMSQ406H425
  rect 4.039x2.159 smd: N(4.2,0) P(-4.2,0)
DFN8_3X3_PAD2_38X1_65
  oval 0.279x0.737 smd: 1(-0.75,-1.393) 2(-0.25,-1.393) 3(0.25,-1.393) 4(0.75,-1.393) 5(0.75,1.393) 6(0.25,1.393) 7(-0.25,1.393) 8(-0.75,1.393)
  rect 2.388x1.651 smd: PAD(0,0)
DFN10_3X3_PAD2_38X1_64
  oval 0.254x0.889 smd: 1(-1,-1.555) 2(-0.5,-1.555) 3(0,-1.555) 4(0.5,-1.555) 5(1,-1.555) 6(1,1.555) 7(0.5,1.555) 8(0,1.555) 9(-0.5,1.555) 10(-1,1.555)
  rect 2.388x1.651 smd: PAD(0,0)
DPAK
  rect 1.6x2.997 smd: 1(-2.286,-4.718) 3(2.286,-4.718)
  rect 5.791x6.198 smd: 4(0,2.445)
L1206-3
  rect 1.6x1.803 smd: 1(-1.397,0) 2(1.397,0)
LED0603
  rect 0.965x0.762 smd: A(0.8,0) C(-0.8,0)
LED0603_A
  rect 0.889x0.787 smd: A(0.845,0) C(-0.845,0)
LED0603H12
  rect 0.787x0.787 smd: A(0.744,0) C(-0.744,0)
LSML208W216H122
  rect 1.168x4.394 smd: 1(-1.651,0) 2(1.651,0)
LSML208W216H122_A
  rect 1.168x4.648 smd: 1(-1.651,0) 2(1.651,0)
LSMSQ157H83_A
  rect 0.965x3.708 smd: 1(-1.181,0) 2(1.181,0)
LSMSQ295H122
  rect 1.778x6.502 smd: 1(-2.362,0) 2(2.362,0)
POWERDI5
  rect 1.143x1.27 smd: 1(-0.92,-3.255) 2(0.92,-3.255)
  rect 3.048x5.156 smd: 3(0,1.312)
POWERDI5060-8
  rect 0.61x1.27 smd: 1(-1.905,-2.67) 2(-0.635,-2.67) 3(0.635,-2.67) 4(1.905,-2.67)
  custom 1.13x1.13 smd: 5(1.905,2.797)
  round 0.127 smd: 6(0.635,2.67) 7(-0.635,2.67) 8(-1.905,2.67)
QFN40_6X6_PAD4_42X4_42
  oval 0.279x0.762 smd: 1(-2.25,-2.886) 2(-1.75,-2.886) 3(-1.25,-2.886) 4(-0.75,-2.886) 5(-0.25,-2.886) 6(0.25,-2.886) 7(0.75,-2.886) 8(1.25,-2.886) 9(1.75,-2.886) 10(2.25,-2.886) 21(2.25,2.886) 22(1.75,2.886) 23(1.25,2.886) 24(0.75,2.886) 25(0.25,2.886) 26(-0.25,2.886) 27(-0.75,2.886) 28(-1.25,2.886) 29(-1.75,2.886) 30(-2.25,2.886)
  oval 0.762x0.279 smd: 11(2.886,-2.25) 12(2.886,-1.75) 13(2.886,-1.25) 14(2.886,-0.75) 15(2.886,-0.25) 16(2.886,0.25) 17(2.886,0.75) 18(2.886,1.25) 19(2.886,1.75) 20(2.886,2.25) 31(-2.886,2.25) 32(-2.886,1.75) 33(-2.886,1.25) 34(-2.886,0.75) 35(-2.886,0.25) 36(-2.886,-0.25) 37(-2.886,-0.75) 38(-2.886,-1.25) 39(-2.886,-1.75) 40(-2.886,-2.25)
  rect 4.42x4.42 smd: PAD(0,0)
R0402
  rect 0.533x0.635 smd: 1(-0.45,0) 2(0.45,0)
R0603
  rect 0.787x0.991 smd: 1(-0.85,0) 2(0.85,0)
R0612
  rect 0.94x3.2 smd: 1(-0.82,0) 2(0.82,0)
R0805
  rect 1.041x1.397 smd: 1(-0.95,0) 2(0.95,0)
R1206
  rect 1.041x1.753 smd: 1(-1.5,0) 2(1.5,0)
R1206_A
  rect 0.889x1.753 smd: 1(-1.6,0) 2(1.6,0)
R1206H38
  rect 1.092x1.6 smd: 1(-1.562,0) 2(1.562,0)
SMA
  rect 2.032x2.032 smd: A(1.994,0) C(-1.994,0)
SO8
  rect 0.61x2.184 smd: 1(-1.905,-2.54) 2(-0.635,-2.54) 3(0.635,-2.54) 4(1.905,-2.54) 5(1.905,2.54) 6(0.635,2.54) 7(-0.635,2.54) 8(-1.905,2.54)
SOD123FL
  rect 0.914x1.219 smd: A(1.638,0) C(-1.638,0)
SOD523_B
  rect 0.813x0.61 smd: A(0.85,0) C(-0.85,0)
SOD523F
  rect 0.787x0.508 smd: A(1,0) C(-1,0)
SOT1205
  rect 0.711x1.143 smd: 1(-1.905,-3.278) 2(-0.635,-3.278) 3(0.635,-3.278) 4(1.905,-3.278)
  custom 0.495x0.495 smd: 5(1.905,2.26) 7(-0.635,2.26)
  round 0.127 smd: 6(0.635,2.54) 8(-1.905,2.54)
SOT1289
  rect 1.448x1.6 smd: 1(-2.776,-1.065) 2(-2.776,1.065)
  rect 4.953x3.683 smd: 3(1.024,0)
TSOT23_6
  rect 0.61x1.219 smd: 1(-0.95,-1.31) 2(0,-1.31) 3(0.95,-1.31) 4(0.95,1.31) 5(0,1.31) 6(-0.95,1.31)
unnamed
  round 4.445 hole 3.175 unplated: (0,0)

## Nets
AGND: C1.1 C2.1 C4.1 C6.1 C7.1 C8.1 C9.1 C10.2(N2) C11.2(N2) C12.N(N2) C13.1 C14.1 C15.1 C16.1 C17.2(N2) C18.1 C19.1 C20.1 C21.1 C22.2(N2) C23.1 C26.1 C31.1 C32.1 C33.1 C35.N(N2) C36.N(N2) C37.1 C38.1 C39.1 C40.1 C42.1 C43.N(N2) C44.1 C46.N(N2) C47.1 C48.1 C49.1 C50.1 C54.1 C55.1 C56.1 C57.1 C58.N(N2) C59.N(N2) C60.N(N2) C61.N(N2) C62.1 D5.A(P) DS2.C EN.3(N3) L8.2(N2) P5.3(N3) P6.3(N3) Q1.1 Q1.2 Q1.3(S3) R4.1 R6.1 R7.1 R24.1 R26.2(N2) R28.2(N2) R31.1 R36.2(N2) R37.1 R38.2(N2) R39.2(N2) R45.2(N2) R55.2(N2) TIMER.1 TP1.1(N1) TP6.1(N1) TP35.1(N1) TP37.1(N1) TP39.1(N1) TP41.1(N1) TP42.1(N1) TP43.1(N1) TP45.1(N1) U1.PAD U2.2 U2.3 U3.2 U3.8 U3.13 U3.35 U3.38 U3.PAD U4.4 U4.PAD
PVIN: C15.2(N2) C16.2(N2) C20.2(N2) C23.2(N2) C62.2(N2) D9.A(P) L9.2(N2) R3.1 R53.1 U3.14 U3.37
VIN: C8.2(N2) C9.2(N2) C13.2(N2) E1.1 Q3.1 Q3.2 Q3.3(S3) R13.1 R50.1 R52.1 TP44.1(N1) U2.6 VIN.1(N1)
VIN1: C42.2(N2) C43.P Q2.5 Q2.6 Q5.4 R11.2(N2) R50.2(N2) R51.2(N2) U1.1 U4.7(VOUT)
VIN2: C1.2(N2) C2.2(N2) C12.P C48.2(N2) C50.2(N2) D3.A(P) L2.2(N2) R1.2(N2) R58.2(N2) U3.19
EN/UVLO: R22.1 U3.22
FAULT: DS3.C EN.1 FAULT.1(N1) U4.6
FSEL4A: R23.2(N2) R24.2(N2) U3.12
FSEL4B: R27.1 R28.1 U3.17
INTVCC: C19.2(N2) R17.1 R19.2(N2) R23.1 R27.2(N2) R29.1 U3.28
PG1: PG1.1(N1) R14.1 U3.1
PG2: PG2.1(N1) R15.1 U3.10
PG3: PG3.1(N1) R18.1 R25.2(N2) U3.40
PG4: PG4.1(N1) R19.1 U3.11
POREN: POREN.1(N1) R25.1 U3.39
SYNC: R26.1 R29.2(N2) SYNC.1(N1) U3.33
UNNAMED_5_CAP_I17_N2: C56.2(N2) E3.2(N2) L9.1
UNNAMED_10_CAP_I43_N1: C41.1 D10.A(P) Q2.1 Q2.3(S) Q4.3(S) Q5.3(S)
UNNAMED_10_CAP_I43_N2: C41.2(N2) D10.C Q2.2 Q2.4 Q4.1 Q5.1 U4.8
UNNAMED_10_CAP_I46_N1: C53.1 C54.2(N2)
UNNAMED_10_CAP_I46_N2: C53.2(N2) Q2.7 Q2.8 Q4.4 R43.1 R57.2(N2) VBATT.1(N1)
UNNAMED_10_CN3P_I18_N1: D6.C LED_DRIVE.1
UNNAMED_10_CN3P_I18_N2: D7.A(P) D8.A(P) LED_DRIVE.2 LED_DRIVE.3(N3)
UNNAMED_10_DIO_I19_P: D6.A(P) R41.1
UNNAMED_10_DIO_I22_N: D8.C DS3.A(P)
UNNAMED_10_DIO_I50_N: D7.C DS2.A(P)
UNNAMED_10_DIOZNR_I12_N: D4.C D5.C
UNNAMED_10_DIOZNR_I13_P: D4.A(P) R41.2(N2) R42.1 R57.1 U4.1
UNNAMED_10_LINLTC4367_I17_OV: R44.2(N2) R45.1 U4.3
UNNAMED_10_LINLTC4367_I17_SHDNN: R42.2(N2) U4.5
UNNAMED_10_LINLTC4367_I17_UV: R43.2(N2) R44.1 U4.2
UNNAMED_11_CAP_I15_N2: C4.2(N2) TIMER.3(N3)
UNNAMED_11_CAP_I88_N2: C7.2(N2) Q3.5 Q3.6 Q3.7 Q3.8 R9.2(N2) R49.2(N2) R52.2(N2) U1.10 U2.1(VIN) VBACKUP.1(N1)
UNNAMED_11_CN3P_I14_N1: CHRG_LED.1 DS1.C
UNNAMED_11_CN3P_I14_N2: CHRG_LED.2 U1.7
UNNAMED_11_CN3P_I18_N2: TIMER.2 U1.6(TIMER)
UNNAMED_11_CN3P_I31_N1: ICHARGE.1 R4.2(N2)
UNNAMED_11_CN3P_I31_N2: ICHARGE.2 R2.2(N2) U1.3
UNNAMED_11_CN3P_I31_N3: ICHARGE.3(N3) R7.2(N2)
UNNAMED_11_CN3P_I34_N1: NTC.1(N1) P2.1
UNNAMED_11_CN3P_I34_N2: P2.2 R5.1 U1.5
UNNAMED_11_CN3P_I34_N3: P2.3(N3) R6.2(N2)
UNNAMED_11_CN3P_I68_N2: CHARGER_EN.1(N1) EN.2 U1.2
UNNAMED_11_CN3P_I82_N1: P13.1 R9.1
UNNAMED_11_CN3P_I82_N3: P13.3(N3) R49.1
UNNAMED_11_CNTP1P_I56_N1: PROG.1(N1) R2.1
UNNAMED_11_DIOLED_I76_P: DS1.A(P) R11.1
UNNAMED_11_LINLTC4079_I19_FB: P13.2 R8.2(N2) U1.9
UNNAMED_11_LINLTC4079_I19_FBG: R8.1 U1.8
UNNAMED_11_LINLTC4079_I19_NTCBI: R5.2(N2) U1.4
UNNAMED_11_LINLTC4412_I41_GATE: Q3.4 U2.5
UNNAMED_11_LINLTC4412_I41_STAT: R13.2(N2) U2.4
UNNAMED_12_CAP_I13_N1: C30.1 R35.1 R37.2(N2) U3.24
UNNAMED_12_CAP_I27_N1: C29.1 R33.1 R38.1 U3.26
UNNAMED_12_CAP_I38_N1: C28.1 R34.1 R39.1 U3.25
UNNAMED_12_CAP_I47_N2: C26.2(N2) R40.2(N2) R54.1 U3.34
UNNAMED_12_CAP_I51_N1: C27.1 R32.1 R36.1 U3.27
UNNAMED_12_CAP_I102_N1: C10.1 P5.1 P5.2 TRKSS1.1(N1) U3.21
UNNAMED_12_CAP_I105_N1: C11.1 P6.1 P6.2 TRKSS2.1(N1) U3.20
UNNAMED_12_CAP_I135_N1: C25.1 R21.2(N2)
UNNAMED_12_CAP_I135_N2: C25.2(N2) L5.1 U3.6 U3.7
UNNAMED_12_CAP_I136_N1: C24.1 R20.2(N2)
UNNAMED_12_CAP_I136_N2: C24.2(N2) L4.1 U3.3
UNNAMED_12_CAP_I137_N1: C22.1 U3.31
UNNAMED_12_CAP_I161_N1: C17.1 D3.C D9.C R3.2(N2) R22.2(N2) U3.23(VIN)
UNNAMED_12_CAP_I178_N1: C45.1 D2.1 D2.2 L1.1 Q1.5 Q1.6 Q1.7 Q1.8
UNNAMED_12_CAP_I178_N2: C31.2(N2) C45.2(N2) C47.2(N2) D1.1 D1.2 D2.3(C) L8.1
UNNAMED_12_CAP_I197_N2: C14.2(N2) C49.2(N2) E1.2(N2) L2.1
UNNAMED_12_CAP_I223_N2: C21.2(N2) U3.16
UNNAMED_12_CN3P_I211_N1: P14.1 R55.1
UNNAMED_12_CN3P_I211_N2: P14.2 RUN3.1(N1) U3.30
UNNAMED_12_CN3P_I211_N3: P14.3(N3) R17.2(N2)
UNNAMED_12_CNTP1P_I217_N1: RST_N.1(N1) U3.32
UNNAMED_12_ICLT8603_I134_BST1: R20.1 U3.4
UNNAMED_12_ICLT8603_I134_BST2: R21.1 U3.5
UNNAMED_12_ICLT8603_I134_GATE4: Q1.4 U3.15
UNNAMED_12_ICLT8603_I134_ISN4: L1.2(N2) R1.1 R58.1 U3.18
UNNAMED_12_ICLT8603_I134_RT: R31.2(N2) U3.29
UNNAMED_12_ICLT8603_I134_SW3: L3.1 U3.36
VOUT1: C29.2(N2) C33.2(N2) C37.2(N2) C58.P C59.P L4.2(N2) R14.2(N2) R15.2(N2) R18.2(N2) R33.2(N2) R54.2(N2) VOUT1.1(N1)
VOUT2: C18.2(N2) C28.2(N2) C38.2(N2) C44.2(N2) C60.P C61.P L5.2(N2) R34.2(N2) R40.1 U3.9 VOUT2.1(N1)
VOUT3: C27.2(N2) C32.2(N2) C39.2(N2) L3.2(N2) R32.2(N2) VOUT3.1(N1)
VOUT4: C6.2(N2) C30.2(N2) C35.P C36.P C40.2(N2) C46.P C55.2(N2) C57.2(N2) D1.3(C) E3.1 R35.2(N2) R51.1 R53.2(N2) VOUT4.1(N1)

Pads without a net: CHRG_LED 3

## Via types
v1: diameter 0.61, hole 0.305, TOP to BOTTOM, 1360 vias
v2: diameter 0.457, hole 0.203, TOP to BOTTOM, 22 vias

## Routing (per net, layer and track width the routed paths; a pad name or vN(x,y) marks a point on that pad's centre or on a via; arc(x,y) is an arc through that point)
AGND: length 68.8
  TOP w0.203: 17.78,87.27 v1(17.78,87.02)
  TOP w0.254: 62.75,30.84 62.7,30.84 62.31,30.46 U3.8 60.6,30.46 60.17,30.03 v1(60.16,30.03) ; v1(60.16,27.36) 60.26,27.46 U3.2 61.69,27.46 62.23,26.92 62.48,26.67 ; v1(59.27,30.92) 59.67,31.31 U3.13 59.67,32.62 60.68,33.63 60.68,33.78 ; U3.38 59.67,26.96 59.27,27.35 v1(59.27,27.36) ; 58.17,25.91 U3.35 58.17,27.15 v1(58.38,27.36) ; U4.4 v1(21.97,62.36)
  TOP w0.305: 58.17,25.91 58.17,24.96 57.32,24.11 C26.1
  TOP w0.508: 12.57,4.26 P6.3 ; P6.3 14.61,4.26 ; P6.3 13.59,3.24 ; 27.19,88.05 R6.1 ; R6.1 27.94,87.4 ; R6.1 28.69,88.05 ; TIMER.1 17.78,97.03 ; TIMER.1 16.76,96.01 ; TIMER.1 18.8,96.01 ; 24,4.26 P5.3 ; P5.3 26.04,4.26 ; P5.3 25.02,3.24 ; R4.1 40.13,96.01 ; U2.2 v1(60.34,65.91) ; 46.61,96.01 EN.3 ; EN.3 48.64,96.01 ; EN.3 47.62,97.03
  L2_GND w0.508: 13.59,3.24 P6.3 ; P6.3 12.57,4.26 ; P6.3 14.61,4.26 ; P5.3 26.04,4.26 ; P5.3 24,4.26 ; P5.3 25.02,3.24 ; EN.3 47.62,97.03 ; EN.3 48.64,96.01 ; EN.3 46.61,96.01 ; 16.76,96.01 TIMER.1 ; TIMER.1 17.78,97.03 ; TIMER.1 18.8,96.01
  L3_PWR w0.508: 48.64,96.01 EN.3 46.61,96.01 ; 24,4.26 P5.3 ; P5.3 26.04,4.26 ; P5.3 25.02,3.24 ; 12.57,4.26 P6.3 ; P6.3 13.59,3.24 ; P6.3 14.61,4.26 ; 16.76,96.01 TIMER.1 17.78,97.03
  BOTTOM w0.203: v1(77.47,29.08) 77.47,29.46 77.01,29.92 C61.N
  BOTTOM w0.508: TIMER.1 17.78,97.03 ; TIMER.1 16.76,96.01 ; TIMER.1 18.8,96.01 ; P6.3 14.61,4.26 ; P6.3 12.57,4.26 ; P6.3 13.59,3.24 ; EN.3 47.62,97.03 ; EN.3 46.61,96.01 ; EN.3 48.64,96.01 ; 24,4.26 P5.3 ; P5.3 26.04,4.26 ; P5.3 25.02,3.24
  vias: v1(3.43,53.34) v1(3.43,52.45) v1(3.68,46.61) v1(3.68,45.09) v1(3.68,43.56) v1(3.68,42.04) v1(3.68,40.64) v1(3.68,39.12) v1(3.68,37.72) v1(3.68,36.32) v1(3.68,34.8) v1(3.66,23.53) v1(3.66,20.99) v1(3.66,18.45) v1(3.66,15.91) v1(3.66,13.37) v1(3.66,10.83) v1(3.81,33.4) v1(4.06,47.88) v1(4.19,32.13) v1(4.32,53.34) v1(4.32,52.45) v1(4.7,48.77) v1(4.81,43.35) v1(4.81,42.08) v1(5.21,53.34) v1(5.21,52.45) v1(5.46,31.75) v1(5.46,30.94) v1(5.84,49.15) v1(6.2,23.53) v1(6.2,20.99) v1(6.2,18.45) v1(6.2,15.91) v1(6.2,13.37) v1(6.2,10.83) v1(6.86,31.75) v1(6.86,30.94) v1(7.37,49.15) v1(8.13,31.75) v1(8.13,30.94) v1(8.64,87.25) v1(8.76,49.15) v1(8.99,23.53) v1(8.99,20.99) v1(8.99,18.45) v1(8.99,15.91) v1(8.99,13.37) v1(8.99,10.83) v1(9.02,54.61) v1(10.29,31.75) v1(10.29,30.73) v1(10.41,54.61) v1(10.41,53.21) v1(10.41,51.94) v1(10.41,50.55) v1(10.41,49.28) v1(10.92,30.23) v1(10.92,29.34) v1(11.53,26.07) v1(11.53,23.53) v1(11.53,20.99) v1(11.53,18.45) v1(11.53,15.91) v1(11.53,13.37) v1(11.53,10.83) v1(11.81,30.23) v1(11.81,29.34) v1(12.28,83.54) v1(12.28,81) v1(12.7,30.23) v1(12.7,29.34) v1(13.46,29.34) v1(13.59,31.8) v1(13.59,30.99) v1(13.59,30.23) v1(13.8,83.54) v1(14.07,26.07) v1(14.07,23.53) v1(14.07,20.99) v1(14.07,18.45) v1(14.07,15.91) v1(14.07,13.37) v1(14.07,10.83) v1(14.61,31.8) v1(14.61,30.99) v1(14.61,30.23) v1(14.61,29.34) v1(15.49,30.23) v1(15.49,29.34) v1(16.38,30.23) v1(16.38,29.34) v1(16.61,26.07) v1(16.61,23.53) v1(16.61,20.99) v1(16.61,18.45) v1(16.61,15.91) v1(16.61,13.37) v1(16.61,10.83) v1(17.27,30.23) v1(17.27,29.34) v1(18.16,31.88) v1(18.16,30.99) v1(18.16,30.15) v1(18.16,29.34) v1(19.05,31.88) v1(19.05,30.99) v1(19.05,30.15) v1(19.05,29.34) v1(19.15,26.07) v1(19.15,23.53) v1(19.15,20.99) v1(19.15,18.45) v1(19.15,15.91) v1(19.15,13.37) v1(19.15,10.83) v1(19.94,33.15) v1(19.94,31.88) v1(19.94,30.99) v1(19.94,30.15) v1(19.94,29.34) v1(20.05,48.3) v1(20.05,47.16) v1(20.05,45.89) v1(20.05,44.62) v1(20.05,43.35) v1(20.05,42.08) v1(20.95,31.88) v1(20.95,30.99) v1(20.95,30.15) v1(20.95,29.34) v1(21.32,48.3) v1(21.32,47.16) v1(21.32,45.89) v1(21.32,44.62) v1(21.32,43.35) v1(21.32,42.08) v1(21.64,33.15) v1(21.69,26.07) v1(21.69,23.53) v1(21.69,20.99) v1(21.69,18.45) v1(21.69,15.91) v1(21.69,13.37) v1(21.69,10.83) v1(22.1,31.88) v1(22.1,30.99) v1(22.1,30.15) v1(22.1,29.34) v1(22.47,33.15) v1(22.59,48.3) v1(22.59,47.16) v1(22.59,45.89) v1(22.59,44.62) v1(22.59,43.35) v1(22.59,42.08) v1(23.2,61.98) v1(23.11,30.15) v1(23.11,29.34) v1(23.21,60.96) v1(23.28,33.15) v1(23.24,31.75) v1(23.24,30.99) v1(23.86,48.3) v1(23.86,47.16) v1(23.86,45.89) v1(23.86,44.62) v1(23.86,43.35) v1(23.86,42.08) v1(23.95,61.98) v1(24.01,60.96) v1(24.09,33.15) v1(24.09,31.75) v1(24.23,26.07) v1(24.23,23.53) v1(24.23,20.99) v1(24.23,18.45) v1(24.23,15.91) v1(24.23,13.37) v1(24.23,10.83) v1(25.06,29.59) v1(25.13,49.57) v1(25.13,48.3) v1(25.13,47.16) v1(25.13,45.89) v1(25.13,44.62) v1(25.13,43.35) v1(25.13,42.08) v1(25.91,29.59) v1(26.4,49.57) v1(26.4,48.3) v1(26.4,47.16) v1(26.4,45.89) v1(26.4,44.62) v1(26.4,43.35) v1(26.4,42.08) v1(26.71,33.2) v1(26.71,31.75) v1(26.71,30.48) v1(26.77,26.07) v1(26.77,23.53) v1(26.77,20.99) v1(26.77,18.45) v1(26.77,15.91) v1(26.77,13.37) v1(26.77,10.83) v1(27.18,60.67) v1(27.18,59.82) v1(27.56,33.2) v1(27.56,31.75) v1(27.56,30.48) v1(27.67,49.57) v1(27.67,48.3) v1(27.67,47.16) v1(27.67,45.89) v1(27.67,44.62) v1(27.67,43.35) v1(27.67,42.08) v1(27.94,87.15) v1(28.07,60.67) v1(28.07,59.82) v1(28.96,60.67) v1(28.96,59.82) v1(28.94,49.57) v1(28.94,48.3) v1(28.94,47.16) v1(28.94,45.89) v1(28.94,44.62) v1(28.94,43.35) v1(28.94,42.08) v1(29.31,26.07) v1(29.31,23.53) v1(29.31,20.99) v1(29.31,18.45) v1(29.31,13.37) v1(29.31,10.83) v1(30.21,49.57) v1(30.21,48.3) v1(30.21,47.16) v1(30.21,45.89) v1(30.21,44.62) v1(30.21,43.35) v1(30.21,42.08) v1(30.99,60.67) v1(30.99,59.82) v1(31.48,47.16) v1(31.48,45.89) v1(31.48,44.62) v1(31.48,43.35) v1(31.48,42.08) v1(31.88,60.67) v1(31.88,59.82) v1(31.85,26.07) v1(31.85,23.53) v1(31.85,20.99) v1(31.85,15.91) v1(31.85,13.37) v1(31.85,10.83) v1(32.77,58.25) v1(32.77,57.4) v1(32.75,47.16) v1(32.75,45.89) v1(32.75,44.62) v1(32.75,43.35) v1(32.75,42.08) v1(33.66,58.25) v1(33.66,57.4) v1(34.02,47.16) v1(34.02,45.89) v1(34.02,44.62) v1(34.02,43.35) v1(34.02,42.08) v1(34.39,26.07) v1(34.39,23.53) v1(34.39,18.45) v1(34.39,15.91) v1(34.39,13.37) v1(34.39,10.83) v1(34.54,58.25) v1(34.54,57.4) v1(35.18,87.15) v1(35.29,49.57) v1(35.29,48.3) v1(35.29,47.16) v1(35.29,45.89) v1(35.29,44.62) v1(35.29,43.35) v1(35.29,42.08) v1(35.43,60.67) v1(35.43,59.82) v1(36.32,60.67) v1(36.32,59.82) v1(36.56,49.57) v1(36.56,48.3) v1(36.56,47.16) v1(36.56,45.89) v1(36.56,44.62) v1(36.56,43.35) v1(36.56,42.08) v1(36.58,30.73) v1(36.58,28.45) v1(36.58,27.43) v1(36.58,26.42) v1(36.58,25.4) v1(36.58,24.26) v1(36.7,29.59) v1(36.93,20.99) v1(36.93,18.45) v1(36.93,15.91) v1(36.93,13.37) v1(36.93,10.83) v1(37.46,30.35) v1(37.85,50.04) v1(37.85,49.02) v1(37.85,48.01) v1(37.85,46.99) v1(37.85,45.85) v1(37.85,44.83) v1(37.85,43.81) v1(37.85,42.8) v1(37.85,33.78) v1(38.1,32.26) v1(38.1,30.99) v1(38.48,34.42) v1(38.73,32.89) v1(38.73,31.62) v1(38.99,50.04) v1(38.99,49.02) v1(38.99,48.01) v1(38.99,46.99) v1(38.99,45.85) v1(38.99,44.83) v1(38.99,43.81) v1(38.99,42.8) v1(39.37,33.53) v1(39.37,32.26) v1(39.5,34.42) v1(40.01,32.89) v1(40.13,35.18) v1(40.26,96.01) v1(40.64,34.42) v1(40.64,33.53) v1(41.02,52.83) v1(41.02,51.56) v1(41.02,50.29) v1(41.02,49.02) v1(41.02,47.75) v1(41.02,46.48) v1(41.02,45.21) v1(41.02,43.94) v1(41.02,42.8) v1(41.27,35.43) v1(41.4,26.03) v1(41.4,25.15) v1(41.4,24.26) v1(41.4,23.37) v1(41.4,22.48) v1(41.4,21.59) v1(41.4,20.7) v1(41.4,19.81) v1(41.4,18.92) v1(41.4,17.78) v1(41.4,16.76) v1(41.4,15.75) v1(41.4,14.73) v1(41.4,13.72) v1(41.4,12.7) v1(41.53,92.84) v1(41.53,53.72) v1(41.53,11.43) v1(41.66,34.42) v1(41.66,33.53) v1(41.72,75.18) v1(41.72,72.64) v1(41.72,70.1) v1(42.42,55.24) v1(42.42,54.23) v1(42.55,26.03) v1(42.55,25.15) v1(42.55,24.26) v1(42.55,23.37) v1(42.55,22.48) v1(42.55,21.59) v1(42.55,20.7) v1(42.55,19.81) v1(42.55,18.92) v1(42.55,17.78) v1(42.55,16.76) v1(42.55,15.75) v1(42.55,14.73) v1(42.55,13.72) v1(42.55,12.7) v1(42.67,11.43) v1(43.18,68.33) v1(43.56,55.24) v1(43.56,54.23) v1(43.56,34.42) v1(43.56,33.6) v1(43.56,26.03) v1(43.56,25.15) v1(43.56,24.26) v1(43.56,23.37) v1(43.56,22.48) v1(43.56,21.59) v1(43.56,20.7) v1(43.56,19.81) v1(43.56,18.92) v1(43.56,17.78) v1(43.56,16.76) v1(43.56,15.75) v1(43.56,14.73) v1(43.56,13.72) v1(43.56,12.7) v1(43.69,11.43) v1(44.26,75.18) v1(44.26,72.64) v1(44.26,70.1) v1(44.32,34.42) v1(44.32,33.6) v1(44.58,16.76) v1(44.58,15.75) v1(44.58,14.73) v1(44.58,13.72) v1(44.58,12.7) v1(44.7,68.33) v1(44.7,55.24) v1(44.7,54.23) v1(44.9,9.17) v1(44.9,4.22) v1(44.9,2.95) v1(44.9,1.68) v1(45.09,34.42) v1(45.09,33.6) v1(45.85,55.24) v1(45.85,54.23) v1(46.1,67.82) v1(46.17,4.22) v1(46.17,2.95) v1(46.17,1.68) v1(46.36,34.42) v1(46.36,33.6) v1(46.61,14.61) v1(46.61,13.72) v1(46.61,12.7) v1(46.8,75.18) v1(46.8,72.64) v1(46.8,70.1) v1(46.99,66.93) v1(46.99,55.24) v1(46.99,54.23) v1(47.12,34.42) v1(47.12,33.6) v1(47.44,10.44) v1(47.44,9.17) v1(47.44,5.49) v1(47.44,4.22) v1(47.44,2.95) v1(47.44,1.68) v1(47.62,14.61) v1(47.62,13.72) v1(47.62,12.7) v1(47.88,34.42) v1(47.88,33.6) v1(48.01,66.42) v1(48.77,35.69) v1(48.77,34.67) v1(48.77,13.72) v1(48.77,12.7) v1(48.71,10.44) v1(48.71,9.17) v1(48.71,5.49) v1(48.71,4.22) v1(48.71,2.95) v1(48.71,1.68) v1(49.15,66.42) v1(49.34,75.18) v1(49.34,72.64) v1(49.34,70.1) v1(49.53,35.69) v1(49.53,34.67) v1(49.98,10.44) v1(49.98,9.17) v1(49.98,4.22) v1(49.98,2.95) v1(49.98,1.68) v1(50.04,19.69) v1(50.04,18.8) v1(50.16,17.91) v1(50.29,35.69) v1(50.42,66.42) v1(51.05,19.69) v1(51.05,18.8) v1(51.18,17.91) v1(51.25,4.22) v1(51.25,2.95) v1(51.25,1.68) v1(51.44,67.56) v1(51.44,66.42) v1(51.88,75.18) v1(51.88,72.64) v1(51.88,70.1) v1(51.82,14.48) v1(51.94,19.69) v1(51.94,18.8) v1(52.52,10.44) v1(52.52,9.17) v1(52.52,7.9) v1(52.52,6.63) v1(52.52,5.49) v1(52.52,4.22) v1(52.52,2.95) v1(52.52,1.68) v1(52.7,67.56) v1(52.7,66.42) v1(52.83,14.48) v1(53.79,10.44) v1(53.79,9.17) v1(53.79,7.9) v1(53.79,6.63) v1(53.79,5.49) v1(53.79,4.22) v1(53.79,2.95) v1(53.79,1.68) v1(53.85,14.48) v1(53.98,13.33) v1(54.1,44.5) v1(54.1,43.69) v1(54.1,42.88) v1(54.1,41.99) v1(54.1,41.1) v1(54.1,40.27) v1(54.1,39.37) v1(54.36,54.74) v1(54.42,75.18) v1(54.42,72.64) v1(54.42,70.1) v1(54.48,18.03) v1(54.86,84.25) v1(54.86,83.06) v1(54.86,82.09) v1(54.83,38.48) v1(54.83,37.59) v1(54.99,44.5) v1(54.99,43.69) v1(54.99,42.88) v1(54.95,41.99) v1(54.95,41.1) v1(54.95,40.27) v1(54.99,39.37) v1(54.99,14.48) v1(54.99,13.46) v1(55.06,10.44) v1(55.06,9.17) v1(55.06,7.9) v1(55.06,6.63) v1(55.06,5.49) v1(55.06,4.22) v1(55.06,2.95) v1(55.06,1.68) v1(55.12,18.67) v1(55.12,17.4) v1(55.37,80.64) v1(55.5,54.74) v1(55.68,84.25) v1(55.68,83.06) v1(55.68,82.09) v1(55.75,19.3) v1(55.75,18.03) v1(56.26,80.77) v1(56.39,18.67) v1(56.33,10.44) v1(56.33,9.17) v1(56.33,7.9) v1(56.33,6.63) v1(56.33,5.49) v1(56.33,4.22) v1(56.33,2.95) v1(56.33,1.68) v1(56.61,30.92) v1(56.61,30.03) v1(56.61,29.14) v1(56.61,28.25) v1(56.61,27.36) v1(56.96,75.18) v1(56.96,72.64) v1(56.96,70.1) v1(57.15,22.87) v1(57.15,22.06) v1(57.15,21.21) v1(57.5,30.92) v1(57.5,30.03) v1(57.5,29.14) v1(57.5,28.25) v1(57.5,27.36) v1(57.4,14.48) v1(57.6,10.44) v1(57.6,9.17) v1(57.6,7.9) v1(57.6,6.63) v1(57.6,5.49) v1(57.6,4.22) v1(57.6,2.95) v1(57.6,1.68) v1(58.17,55.75) v1(58.17,54.74) v1(58.38,30.92) v1(58.38,30.03) v1(58.38,29.14) v1(58.38,28.25) v1(58.55,14.99) v1(58.87,10.44) v1(58.87,9.17) v1(58.87,7.9) v1(58.87,6.63) v1(58.87,5.49) v1(58.87,4.22) v1(58.87,2.95) v1(58.87,1.68) v1(59.27,30.03) v1(59.27,29.14) v1(59.27,28.25) v1(59.5,75.18) v1(59.5,72.64) v1(59.5,70.1) v1(59.44,55.75) v1(59.44,54.74) v1(59.44,15.88) v1(59.44,14.1) v1(59.44,12.95) v1(59.44,11.56) v1(60.05,94.27) v1(60.05,93) v1(60.05,91.73) v1(60.16,30.92) v1(60.16,29.14) v1(60.16,28.25) v1(60.14,5.49) v1(60.14,4.22) v1(60.14,2.95) v1(60.14,1.68) v1(60.71,55.75) v1(60.71,54.74) v1(61.32,94.27) v1(61.32,93) v1(61.32,91.73) v1(61.41,5.49) v1(61.41,4.22) v1(61.41,2.95) v1(61.41,1.68) v1(61.98,55.75) v1(61.98,54.74) v1(62.04,72.64) v1(62.04,70.1) v1(62.59,94.27) v1(62.59,93) v1(62.59,91.73) v1(62.61,24.56) v1(62.68,5.49) v1(62.68,4.22) v1(62.68,2.95) v1(62.68,1.68) v1(62.74,67.31) v1(62.74,66.29) v1(62.94,25.31) v1(63.04,21.34) v1(63.25,55.75) v1(63.25,54.74) v1(63.24,35.22) v1(63.24,34.33) v1(63.25,33.52) v1(63.5,25.91) v1(63.58,20.62) v1(63.86,94.27) v1(63.86,93) v1(63.86,91.73) v1(63.88,67.44) v1(63.88,66.29) v1(63.85,25.15) v1(63.88,24.26) v1(63.85,23.37) v1(63.88,22.35) v1(63.95,5.49) v1(63.95,4.22) v1(63.95,2.95) v1(63.95,1.68) v1(64.13,35.23) v1(64.13,34.34) v1(64.13,33.53) v1(64.13,32.51) v1(64.31,21.51) v1(64.58,75.18) v1(64.58,72.64) v1(64.58,70.1) v1(64.52,55.75) v1(64.52,54.74) v1(64.52,20.57) v1(64.77,68.58) v1(64.77,24.26) v1(64.77,23.37) v1(64.77,22.35) v1(65.13,94.27) v1(65.13,93) v1(65.13,91.73) v1(65.15,66.29) v1(65.15,35.18) v1(65.15,34.29) v1(65.22,5.49) v1(65.22,4.22) v1(65.22,2.95) v1(65.22,1.68) v1(65.41,21.46) v1(65.79,55.75) v1(65.79,54.74) v1(66.04,69.85) v1(66.17,35.18) v1(66.17,34.37) v1(66.4,94.27) v1(66.4,93) v1(66.4,91.73) v1(66.49,5.49) v1(66.49,4.22) v1(66.49,2.95) v1(66.49,1.68) v1(67.06,70.87) v1(67.06,55.75) v1(67.06,54.74) v1(67.18,35.18) v1(67.18,34.29) v1(67.67,94.27) v1(67.67,93) v1(67.67,91.73) v1(67.76,5.49) v1(67.76,4.22) v1(67.76,2.95) v1(67.76,1.68) v1(67.94,16.64) v1(68.2,71.75) v1(68.33,35.05) v1(68.94,94.27) v1(68.94,93) v1(68.94,91.73) v1(68.96,36.7) v1(69.09,35.81) v1(69.09,16.64) v1(69.03,5.49) v1(69.03,4.22) v1(69.03,2.95) v1(69.03,1.68) v1(69.34,38.61) v1(69.6,39.62) v1(69.72,37.46) v1(69.85,36.58) v1(69.98,18.92) v1(69.98,17.91) v1(70.21,94.27) v1(70.21,93) v1(70.21,91.73) v1(70.3,5.49) v1(70.3,4.22) v1(70.3,2.95) v1(70.3,1.68) v1(70.36,40.39) v1(70.36,16.64) v1(70.61,38.23) v1(70.61,37.34) v1(71.12,41.15) v1(71.25,17.91) v1(71.37,38.99) v1(71.37,38.1) v1(71.48,94.27) v1(71.48,93) v1(71.48,91.73) v1(71.5,16.64) v1(71.57,5.49) v1(71.57,4.22) v1(71.57,2.95) v1(71.57,1.68) v1(71.63,29.46) v1(71.63,26.54) v1(71.88,41.91) v1(72.14,28.58) v1(72.14,27.3) v1(72.26,39.88) v1(72.26,38.99) v1(72.52,17.91) v1(72.64,42.67) v1(72.75,94.27) v1(72.75,93) v1(72.75,91.73) v1(72.77,16.64) v1(72.84,5.49) v1(72.84,4.22) v1(72.84,2.95) v1(72.84,1.68) v1(72.97,28.58) v1(72.97,27.3) v1(73.02,40.77) v1(73.15,39.88) v1(73.66,43.05) v1(73.79,41.78) v1(73.79,28.58) v1(73.79,27.3) v1(73.79,17.91) v1(74.02,94.27) v1(74.02,93) v1(74.02,91.73) v1(74.04,40.77) v1(74.04,16.64) v1(74.11,5.49) v1(74.11,4.22) v1(74.11,2.95) v1(74.11,1.68) v1(74.93,43.05) v1(74.93,41.66) v1(75.29,94.27) v1(75.29,93) v1(75.29,91.73) v1(75.31,16.64) v1(75.38,5.49) v1(75.38,4.22) v1(75.38,2.95) v1(75.38,1.68) v1(75.56,60.32) v1(75.57,56.82) v1(75.56,56.01) v1(75.95,51.69) v1(76.07,81.15) v1(76.07,79.76) v1(76.07,71.75) v1(76.11,78.27) v1(76.11,76.87) v1(76.11,75.47) v1(76.11,74.2) v1(76.11,72.93) v1(76.2,43.05) v1(76.45,56.81) v1(76.45,56) v1(76.45,16.64) v1(76.56,94.27) v1(76.56,93) v1(76.56,91.73) v1(76.65,5.49) v1(76.65,4.22) v1(76.65,2.95) v1(76.65,1.68) v1(77.35,56.82) v1(77.34,56) v1(77.34,26.29) v1(77.47,81.15) v1(77.47,79.76) v1(77.47,71.75) v1(77.47,60.32) v1(77.47,51.69) v1(77.47,43.05) v1(77.51,78.27) v1(77.51,76.87) v1(77.51,75.47) v1(77.51,74.2) v1(77.51,72.93) v1(77.59,38.53) v1(77.72,16.64) v1(77.83,94.27) v1(77.83,93) v1(77.83,91.73) v1(77.92,5.49) v1(77.92,4.22) v1(77.92,2.95) v1(77.92,1.68) v1(78.36,29.08) v1(78.49,39.43) v1(78.74,43.05) v1(78.99,16.64) v1(79.1,94.27) v1(79.1,93) v1(79.1,91.73) v1(79.19,5.49) v1(79.19,4.22) v1(79.19,2.95) v1(79.19,1.68) v1(79.25,29.08) v1(79.39,40.33) v1(80.01,43.05) v1(80.37,94.27) v1(80.37,93) v1(80.37,91.73) v1(80.39,51.69) v1(80.39,16.64) v1(80.46,5.49) v1(80.46,4.22) v1(80.46,2.95) v1(80.46,1.68) v1(80.64,41.27) v1(81.28,60.32) v1(81.41,56.94) v1(81.41,56.13) v1(81.41,43.05) v1(81.53,16.64) v1(81.64,94.27) v1(81.64,93) v1(81.64,91.73) v1(81.79,51.69) v1(81.73,5.49) v1(81.73,4.22) v1(81.73,2.95) v1(81.73,1.68) v1(81.91,41.27) v1(82.29,56.95) v1(82.32,56.13) v1(82.8,43.05) v1(82.8,16.64) v1(82.91,94.27) v1(82.91,93) v1(82.91,91.73) v1(83,5.49) v1(83,4.22) v1(83,2.95) v1(83,1.68) v1(83.18,60.32) v1(83.19,56.95) v1(83.18,56.13) v1(83.18,51.69) v1(83.18,41.27) v1(83.44,28.83) v1(83.79,30.27) v1(84.08,56.94) v1(84.07,56.12) v1(84.07,16.64) v1(84.2,43.05) v1(84.45,51.69) v1(84.45,41.27) v1(84.45,28.83) v1(84.6,19.86) v1(84.69,31.17) v1(84.97,56.94) v1(84.96,56.13) v1(85.09,60.32) v1(85.34,28.83) v1(85.34,16.64) v1(85.47,91.31) v1(85.47,43.05) v1(85.59,32.07) v1(85.87,19.86) v1(86.36,90.17) v1(86.48,32.97) v1(86.87,43.05) v1(86.99,60.32) v1(87.14,19.86) v1(87.25,58.29) v1(87.38,88.27) v1(87.38,86.87) v1(87.38,85.6) v1(87.38,83.95) v1(87.38,33.27) v1(87.76,44.07) v1(87.88,76.45) v1(88.44,33.25) v1(88.69,89.12) v1(88.69,87.85) v1(88.69,86.58) v1(88.69,85.31) v1(88.69,84.04) v1(88.69,82.77) v1(88.69,81.5) v1(88.69,78.96) v1(89.03,76.45) v1(89.96,89.12) v1(89.96,87.85) v1(89.96,86.58) v1(89.96,85.31) v1(89.96,84.04) v1(89.96,82.77) v1(89.96,81.5) v1(90.17,76.45) v1(91.11,33.32) v1(91.23,89.12) v1(91.23,87.85) v1(91.23,86.58) v1(91.23,85.31) v1(91.23,84.04) v1(91.23,82.77) v1(91.23,81.5) v1(91.23,80.23) v1(91.31,76.45) v1(91.44,77.6) v1(91.69,43.69) v1(91.95,58.55) v1(91.95,46.23) v1(91.95,44.96) v1(91.95,18.8) v1(91.95,17.53) v1(91.95,16.38) v1(92.07,60.32) v1(92.2,96.65) v1(92.5,89.12) v1(92.5,87.85) v1(92.5,86.58) v1(92.5,85.31) v1(92.5,84.04) v1(92.5,82.77) v1(92.5,81.5) v1(92.5,80.23) v1(92.5,78.96) v1(92.5,77.69) v1(92.5,76.42) v1(93.34,93.98) v1(93.34,60.96) v1(93.34,47.12) v1(93.47,50.42) v1(93.47,49.28) v1(93.47,48.13) v1(93.6,8.64) v1(93.6,7.49) v1(93.6,6.1) v1(93.77,89.12) v1(93.77,87.85) v1(93.77,86.58) v1(93.77,85.31) v1(93.77,84.04) v1(93.77,82.77) v1(93.77,81.5) v1(93.77,80.23) v1(93.77,78.96) v1(93.77,77.69) v1(93.77,76.42) v1(93.98,62.23) v1(94.23,36.45) v1(94.23,35.31) v1(94.23,34.29) v1(94.61,71.75) v1(94.61,69.85) v1(94.61,67.95) v1(94.61,66.04) v1(94.61,64.14) v1(94.74,47.12)
PVIN: length 36.5
  TOP w0.203: 59.94,22.23 59.94,21.97 v1(60.2,21.72) ; 59.94,22.23 C15.2 ; 59.94,22.23 v1(59.44,21.72)
  TOP w0.254: 59.44,25.15 59.17,25.41 U3.37
  TOP w0.279: U3.14 59.17,33.25 C20.2
  TOP w0.305: 59.44,25.15 59.44,25.14 C23.2
  L3_PWR w1.016: 59.82,22.1 59.82,22.1 v1(60.2,21.72) v1(59.44,21.72) 59.82,22.1 ; 59.82,22.1 59.82,25.35 61.72,27.25 61.72,31.05 60.24,32.54 v1(60.24,37.34) v1(60.24,38.15)
  BOTTOM w0.203: 59.76,39.88 59.76,38.46 60.07,38.15 v1(60.24,38.15)
  BOTTOM w0.406: v1(60.24,37.34) 57.66,37.34 57.02,36.7 52.92,36.7 52.84,36.63
  BOTTOM w0.635: D9.A 52.84,36.63 R3.1
